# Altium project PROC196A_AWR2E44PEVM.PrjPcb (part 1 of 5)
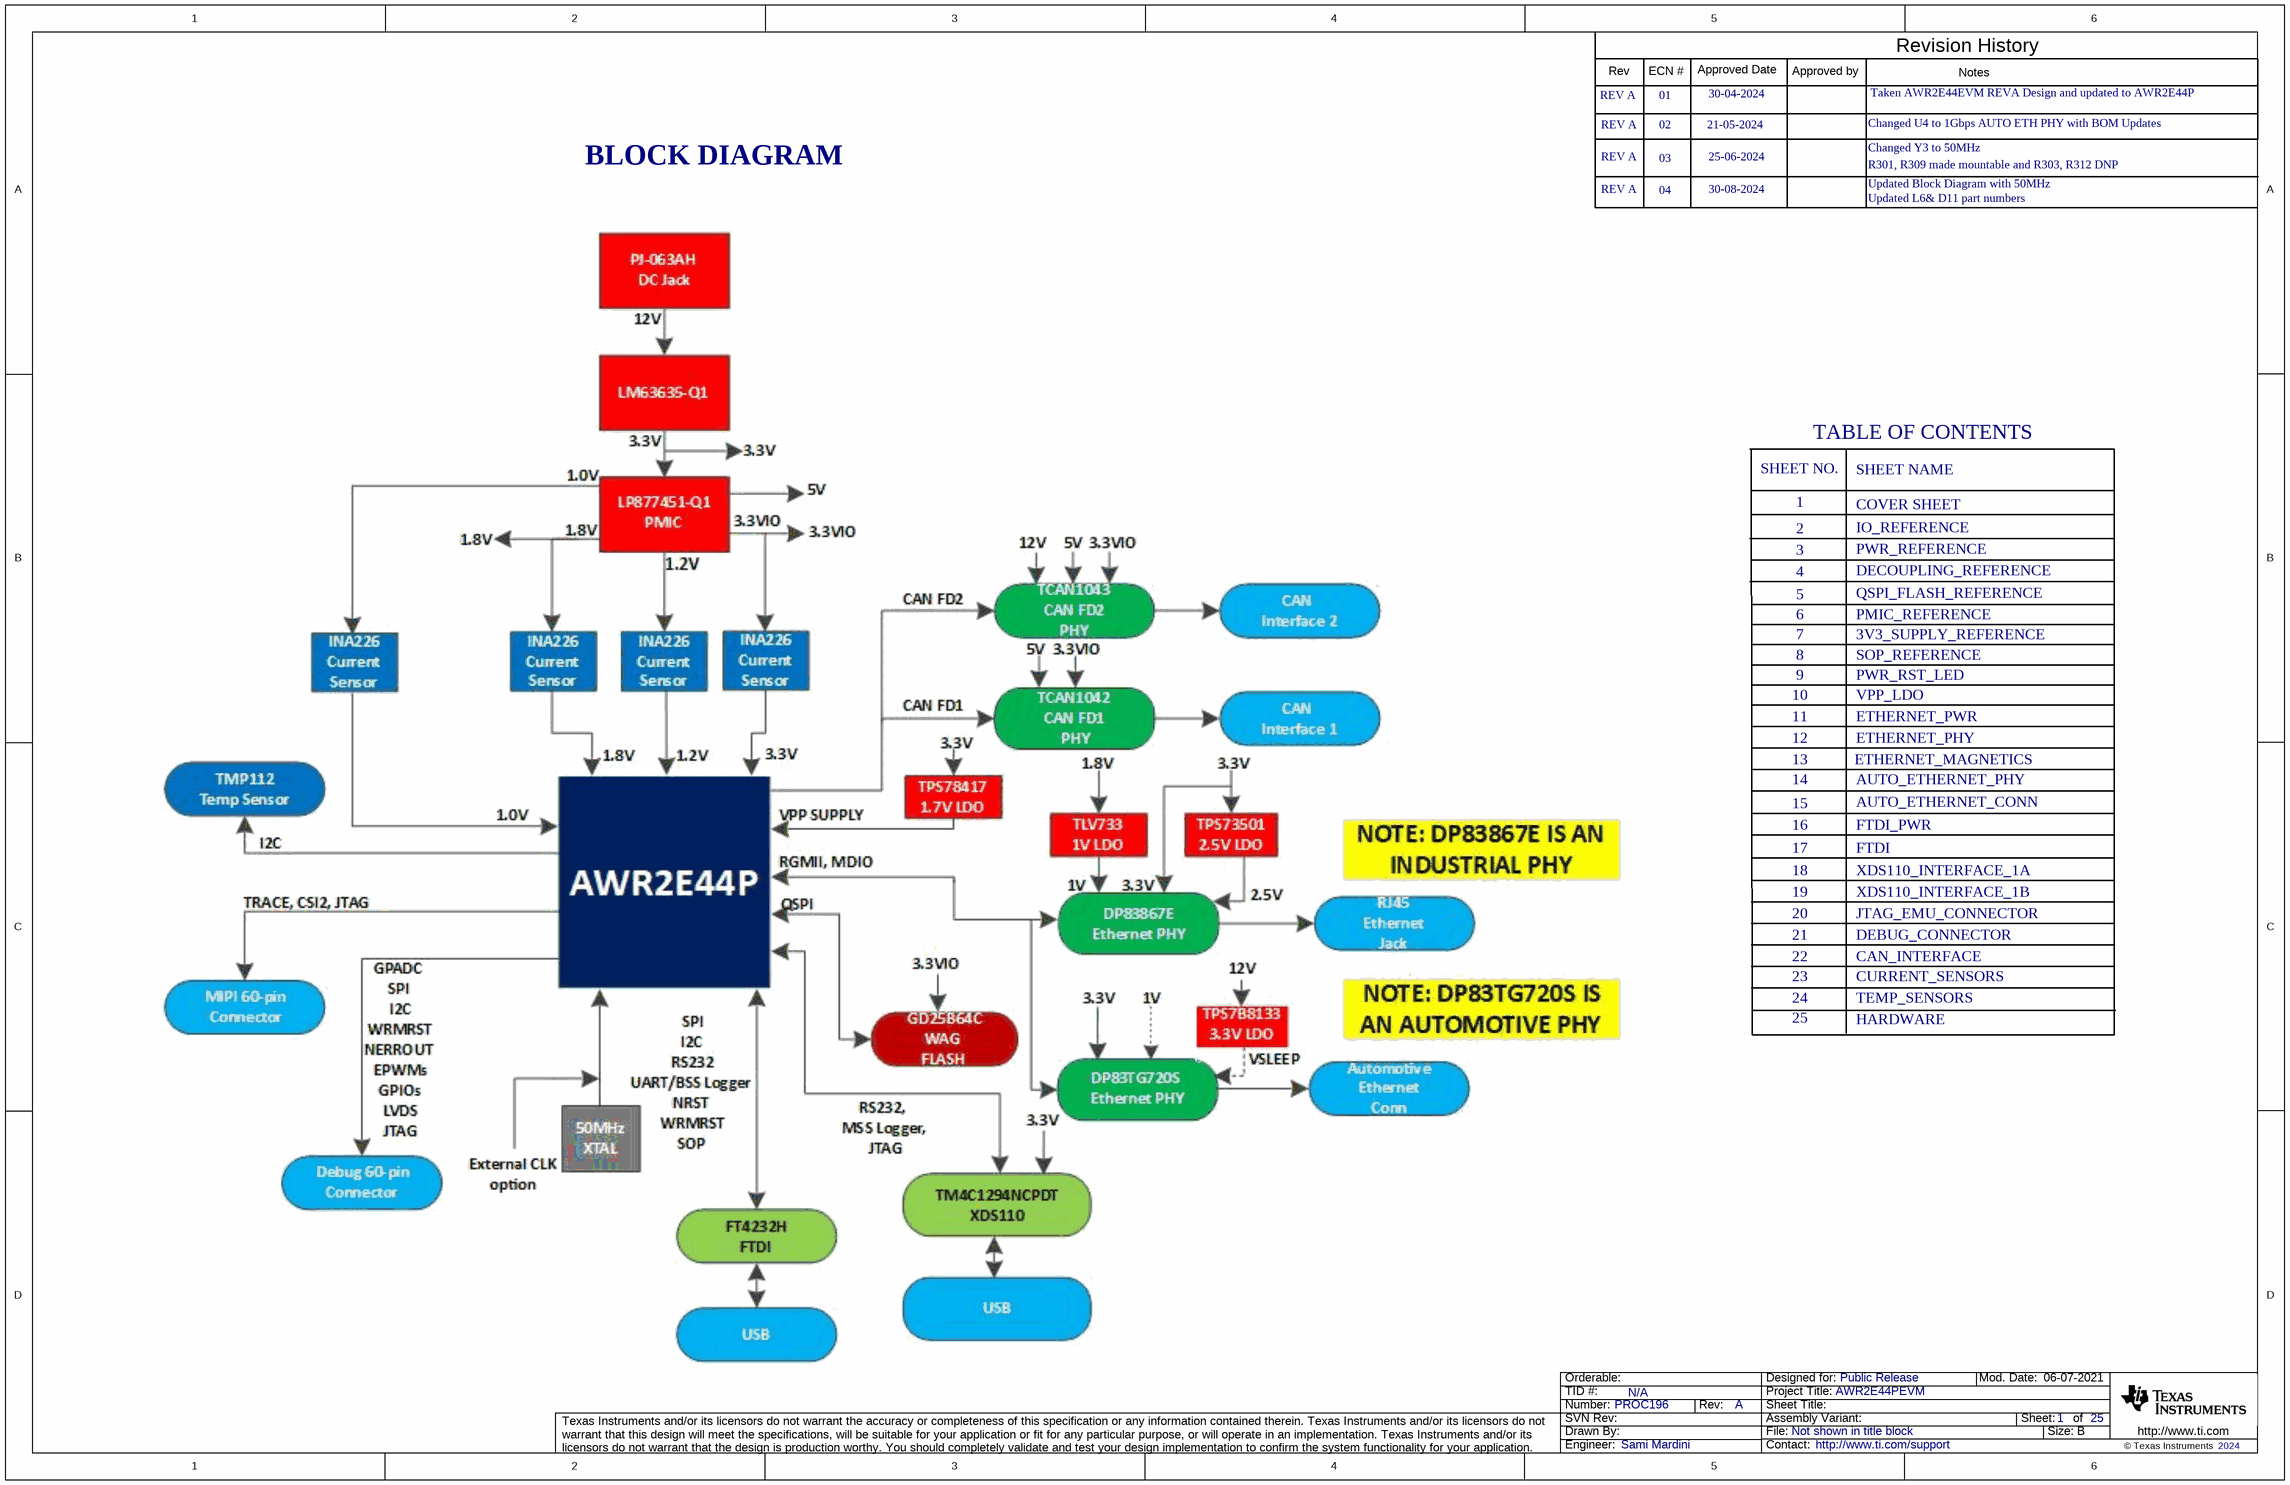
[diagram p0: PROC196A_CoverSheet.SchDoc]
CopyrightYear: 2024; PCB_Layout: Mistral; PCB_Rev: A; PRJ_Customer: Public Release; PRJ_Engineer: Sami Mardini; PRJ_Number: PROC196; PRJ_Title: AWR2E44PEVM; SCH_Rev: A; TechSupport: http://www.ti.com/support; TID: N/A
25 sheets, 736 parts. Net scope: global (net labels, ports and power ports of the same name join across sheets).
Board file: PROC196A_BRD.PcbDoc
Sheets:
  PROC196A_CoverSheet.SchDoc
  PROC196A_IO_Reference.SchDoc
  PROC196A_PWR_Reference.SchDoc
  PROC196A_Decoupling_Reference.SchDoc
  PROC196A_QSPI_Flash_Reference.SchDoc
  PROC196A_PMIC_Reference.SchDoc
  PROC196A_3V3_Supply_Reference.SchDoc
  PROC196A_SOP_Reference.SchDoc
  PROC196A_PWR_RST_LED.SchDoc
  PROC196A_VPP_LDO.SchDoc
  PROC196A_Ethernet_PWR.SchDoc
  PROC196A_Ethernet_PHY.SchDoc
  PROC196A_Ethernet_Magnetics.SchDoc
  PROC196A_Auto_Ethernet_PHY.SchDoc
  PROC196A_Auto_Ethernet_conn.SchDoc
  PROC196A_FTDI_PWR.SchDoc
  PROC196A_FTDI.SchDoc
  PROC196A_XDS110 Interface_1A.SchDoc
  PROC196A_XDS110 Interface_1B.SchDoc
  PROC196A_JTAG_EMU_Connector.SchDoc
  PROC196A_Debug_Connector.SchDoc
  PROC196A_CAN_Interface.SchDoc
  PROC196A_Current_Sensors.SchDoc
  PROC196A_Temp_Sensor.SchDoc
  PROC196A_Hardware.SchDoc

## Sheet PROC196A_CoverSheet.SchDoc
size 431 x 279 mm; Date: Not shown in title block; ApprovedBy: Not shown in title block; CheckedBy: Not shown in title block; Author: Not shown in title block; CompanyName: Not shown in title block; Engineer: Not shown in title block; Organization: Not shown in title block; Address1: Not shown in title block; Address2: Not shown in title block; Address3: Not shown in title block; Address4: Not shown in title block; DocumentNumber: 1; Revision: Use project parameter SCH_Rev; SheetNumber: 1; SheetTotal: 25; PageSetup: Record=PageOptions¦CenterHorizontal=True¦CenterVertical=True¦PrintScale=1.00¦XCorrection=1.00¦YCorrection=1.00¦PrintKind=0¦BorderSize=5000000¦LeftOffset=0¦BottomOffset=0¦Orientation=2¦PaperLength=1000¦PaperWidth=1000¦Scale=100¦PaperSource=15¦PrintQuality=600¦MediaType=1¦DitherType=10¦PaperKind=Letter¦PrintScaleMode=1

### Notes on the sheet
- REV A
- Rev
- 01
- ECN #
- 30-04-2024
- Approved Date
- Approved by
- Taken AWR2E44EVM REVA Design and updated to AWR2E44P
- Revision History
- Notes
- BLOCK DIAGRAM
- 02
- 03
- 21-05-2024
- 25-06-2024
- Changed U4 to 1Gbps AUTO ETH PHY with BOM Updates
- Changed Y3 to 50MHz
- R301, R309 made mountable and R303, R312 DNP
- 04
- 30-08-2024
- Updated Block Diagram with 50MHz
- Updated L6& D11 part numbers
- SHEET NO.
- TABLE OF CONTENTS
- SHEET NAME
- 1
- 2
- 3
- COVER SHEET
- IO_REFERENCE
- PWR_REFERENCE
- 4
- 5
- 6
- DECOUPLING_REFERENCE
- PMIC_REFERENCE
- QSPI_FLASH_REFERENCE
- 10
- 7
- 8
- 9
- PWR_RST_LED
- SOP_REFERENCE
- VPP_LDO
- 3V3_SUPPLY_REFERENCE
- 11
- 12
- 13
- ETHERNET_MAGNETICS
- ETHERNET_PWR
- ETHERNET_PHY
- 15
- 16
- 14
- FTDI_PWR
- AUTO_ETHERNET_CONN
- AUTO_ETHERNET_PHY
- 17
- 18
- 19
- XDS110_INTERFACE_1B
- XDS110_INTERFACE_1A
- FTDI
- 20
- 21
- 22
- JTAG_EMU_CONNECTOR
- DEBUG_CONNECTOR
- CAN_INTERFACE
- 23
- 24
- 25
- HARDWARE
- CURRENT_SENSORS
- TEMP_SENSORS

## Sheet PROC196A_IO_Reference.SchDoc
size A2; Date: Not shown in title block; ApprovedBy: Not shown in title block; CheckedBy: Not shown in title block; Author: Not shown in title block; CompanyName: Not shown in title block; Engineer: Not shown in title block; Organization: Not shown in title block; Address1: Not shown in title block; Address2: Not shown in title block; Address3: Not shown in title block; Address4: Not shown in title block; DocumentNumber: 2; Revision: Use project parameter SCH_Rev; SheetNumber: 2; SheetTotal: 25; PageSetup: Record=PageOptions¦CenterHorizontal=True¦CenterVertical=True¦PrintScale=1.00¦XCorrection=1.00¦YCorrection=1.00¦PrintKind=0¦BorderSize=5000000¦LeftOffset=0¦BottomOffset=0¦Orientation=2¦PaperLength=1000¦PaperWidth=1000¦Scale=100¦PaperSource=15¦PrintQuality=600¦MediaType=1¦DitherType=10¦PaperKind=Letter¦PrintScaleMode=1
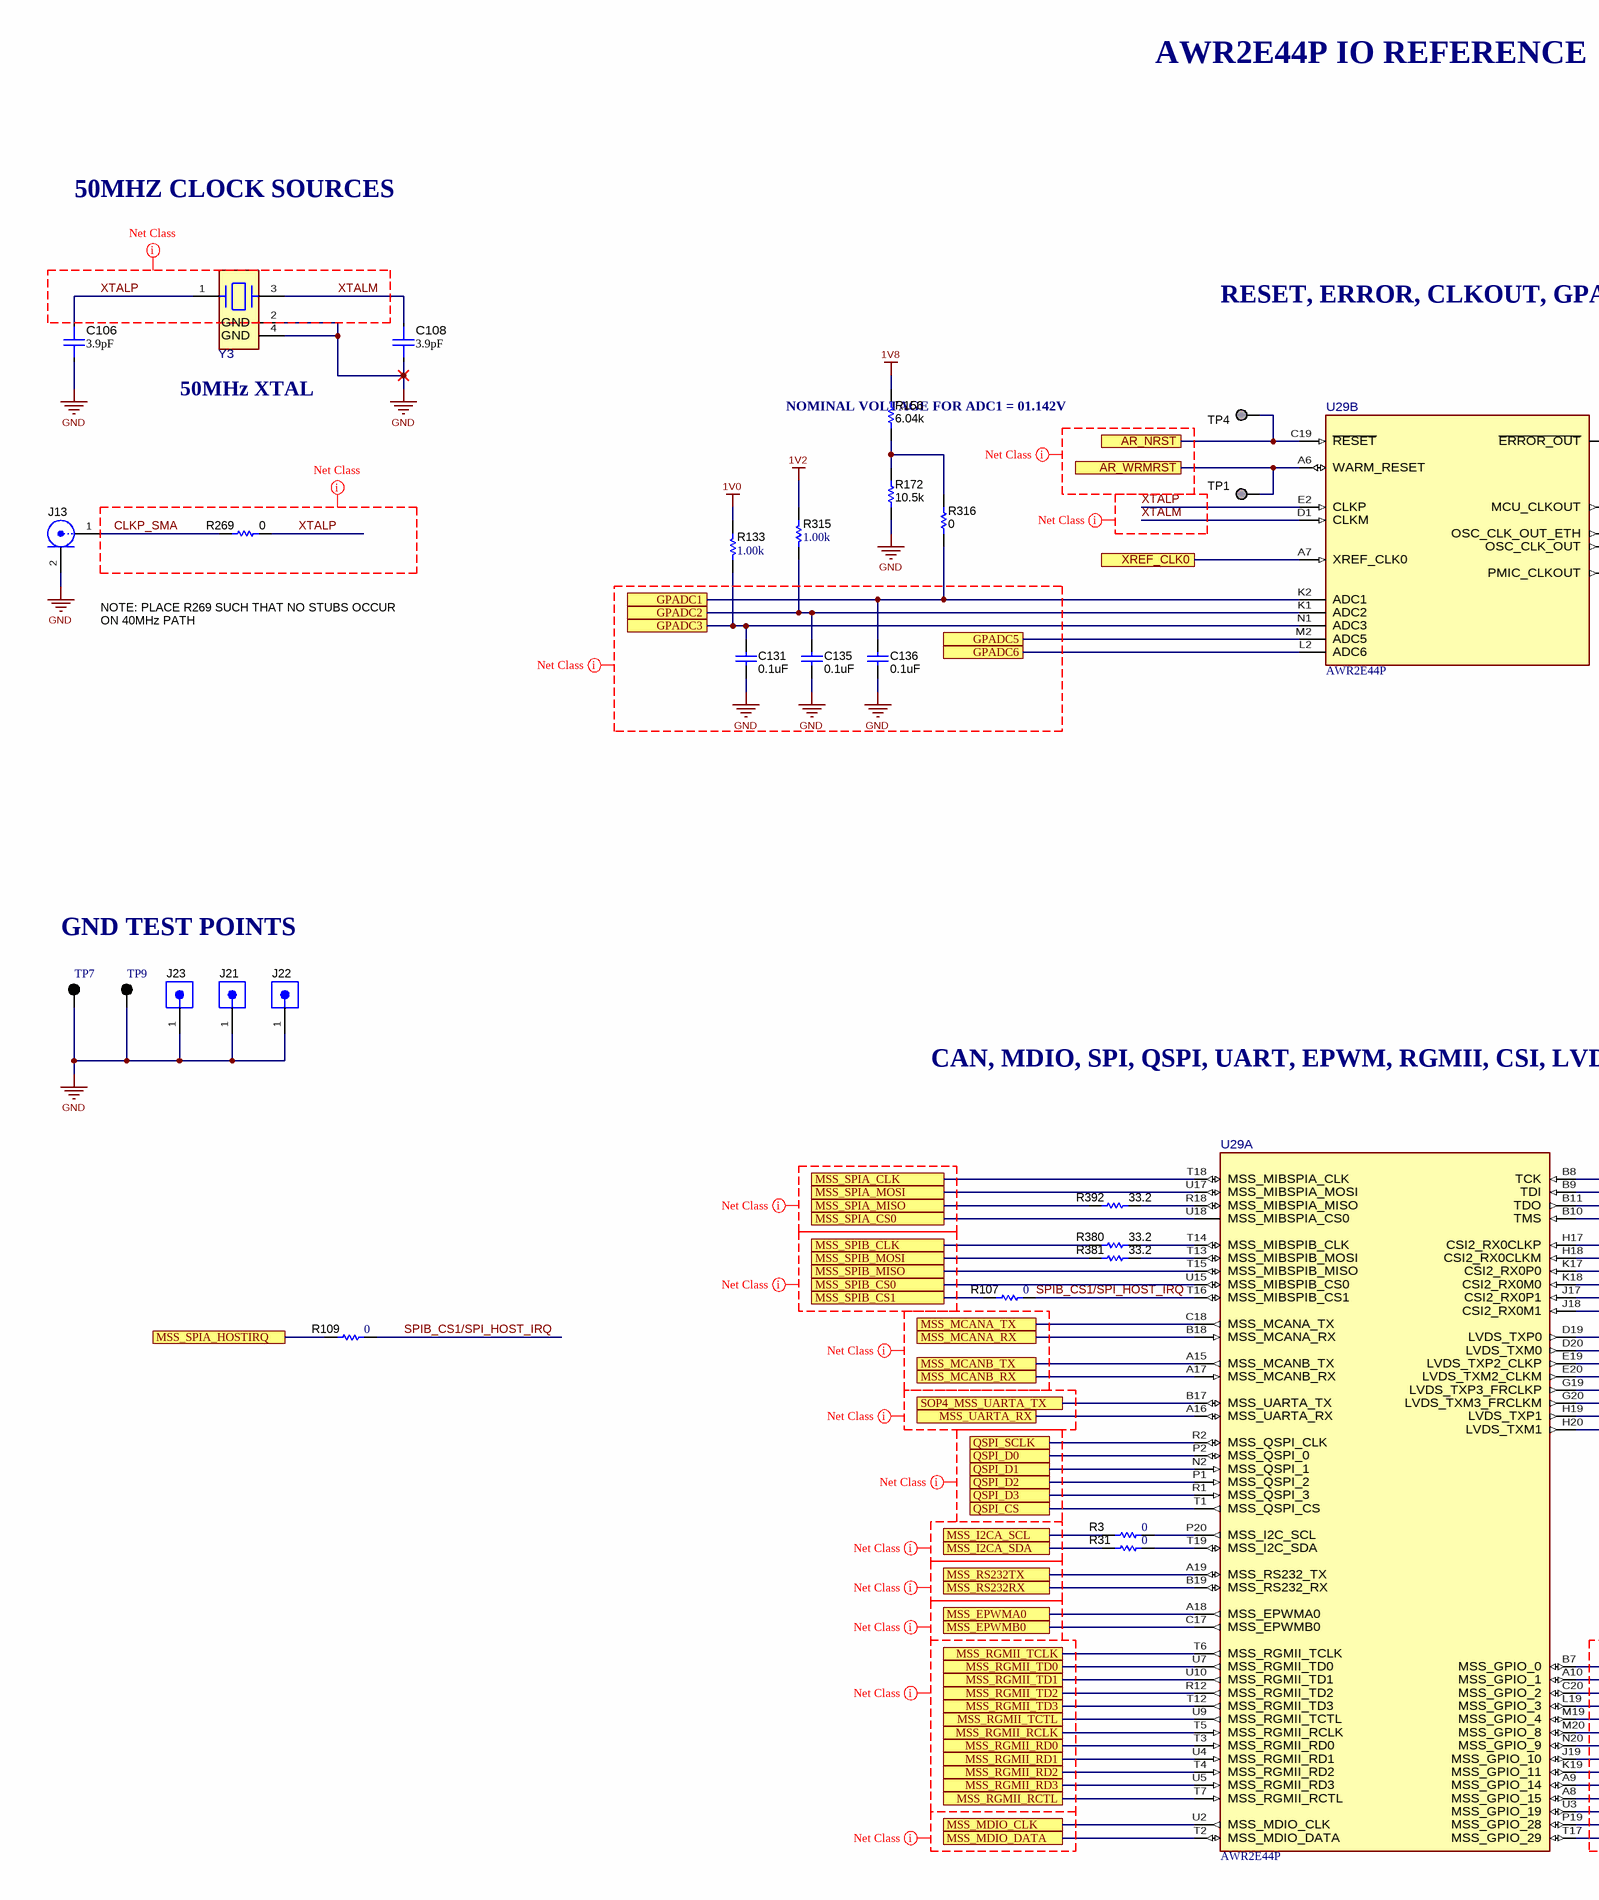
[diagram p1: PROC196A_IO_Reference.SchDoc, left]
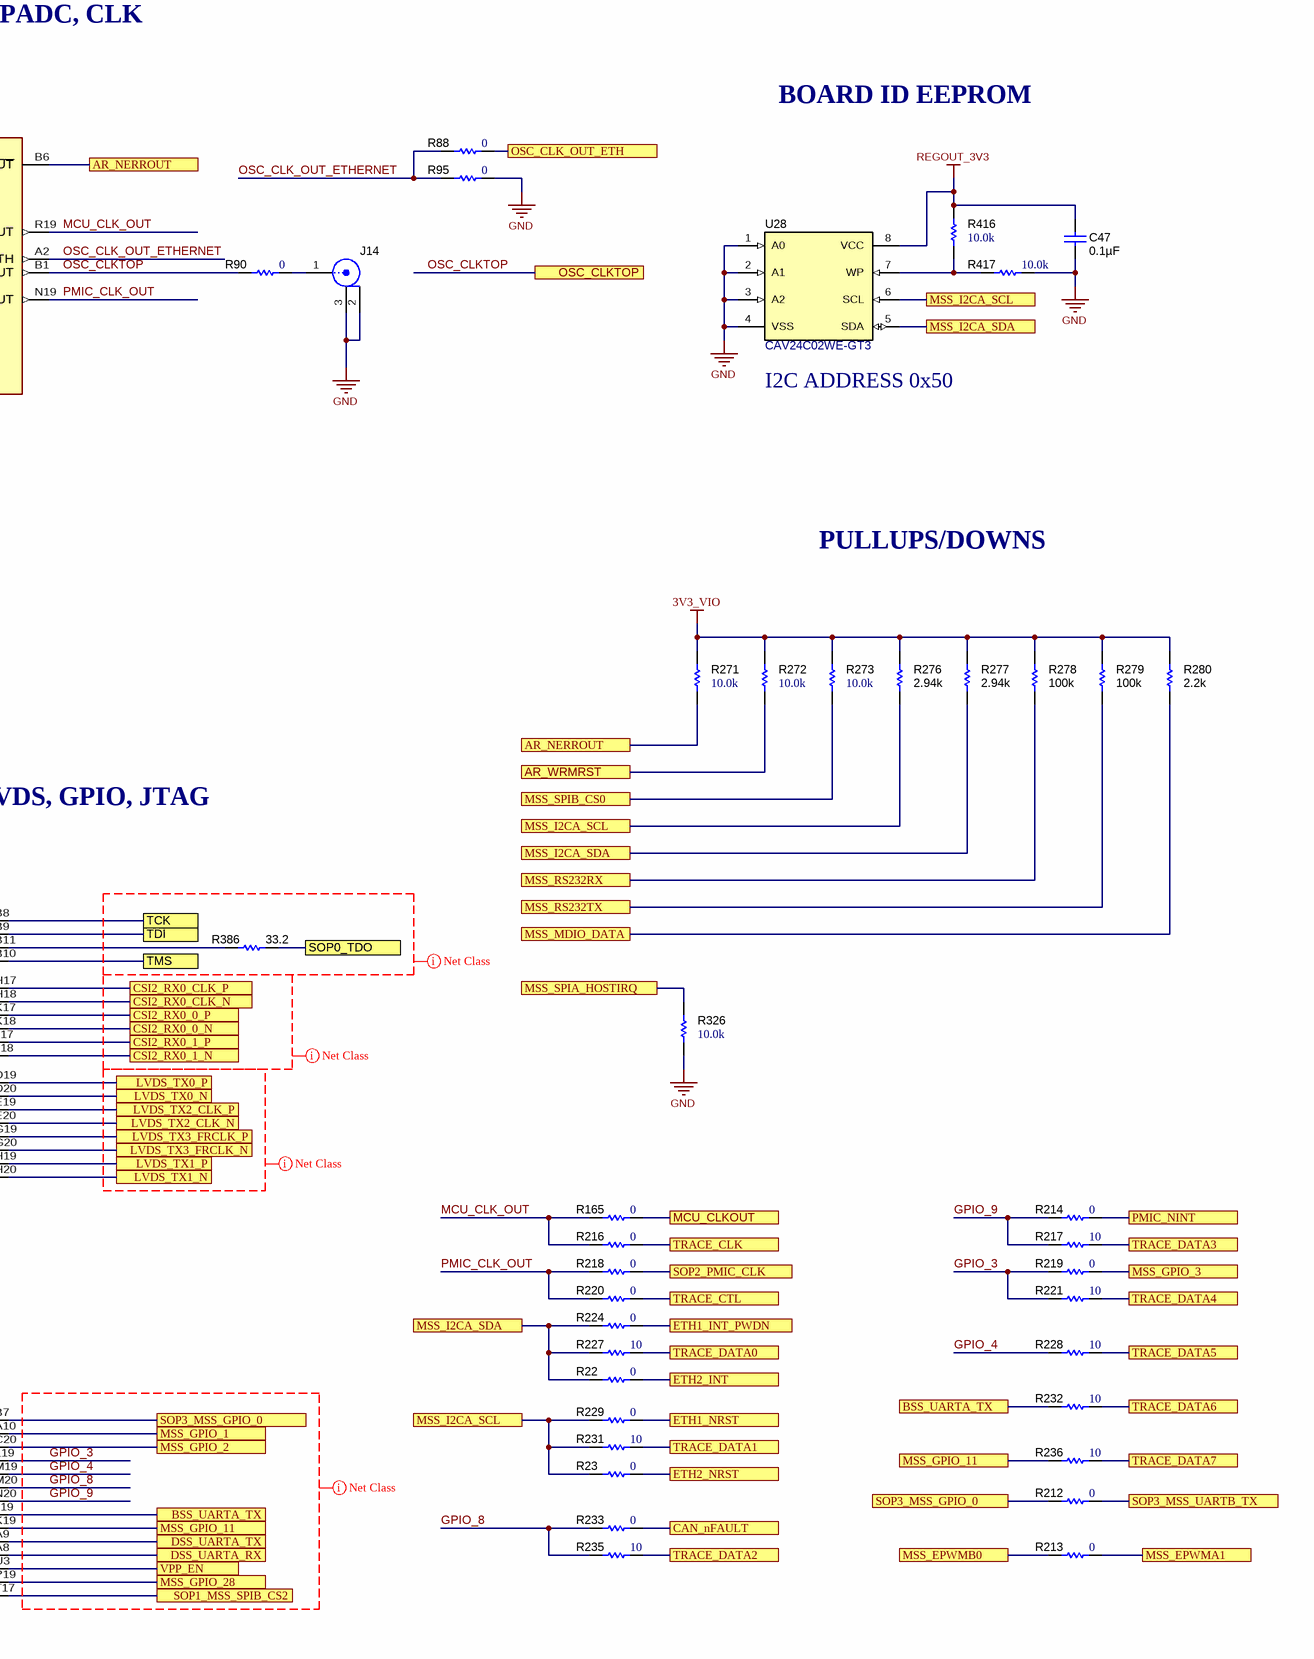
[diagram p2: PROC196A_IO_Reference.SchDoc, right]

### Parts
C47  ValueDisplayed: 0.1µF  [0402L]  (hidden comment: C0402C104K8RACTU)
C106  ValueDisplayed: 3.9pF  [FP-GCM1555C1H3R9BA16D_0402-MFG]  (hidden comment: GCM1555C1H3R9BA16D)
C108  ValueDisplayed: 3.9pF  [FP-GCM1555C1H3R9BA16D_0402-MFG]  (hidden comment: GCM1555C1H3R9BA16D)
C131  ValueDisplayed: 0.1uF  [0402L]  (hidden comment: GCM155R71C104KA55D)
C135  ValueDisplayed: 0.1uF  [0402L]  (hidden comment: GCM155R71C104KA55D)
C136  ValueDisplayed: 0.1uF  [0402L]  (hidden comment: GCM155R71C104KA55D)
J13  142-0711-201  [142-0711-201]  (value not drawn)
J14  128-0711-201  [Johnson_128-0711-201]  (value not drawn)
J21  GBC01SFBN-M30  [Sullins_GBC01SFBN-M30]  (value not drawn)
J22  GBC01SFBN-M30  [Sullins_GBC01SFBN-M30]  (value not drawn)
J23  GBC01SFBN-M30  [Sullins_GBC01SFBN-M30]  (value not drawn)
R3  ValueDisplayed: 0  [0402L]  (hidden comment: ERJ-2GE0R00X)
R22  ValueDisplayed: 0  [0402L]  (hidden comment: ERJ-2GE0R00X)
R23  ValueDisplayed: 0  [0402L]  (hidden comment: ERJ-2GE0R00X)
R31  ValueDisplayed: 0  [0402L]  (hidden comment: ERJ-2GE0R00X)
R88  ValueDisplayed: 0  [0402L]  (hidden comment: ERJ-2GE0R00X)
R90  ValueDisplayed: 0  [0402L]  (hidden comment: ERJ-2GE0R00X)
R95  ValueDisplayed: 0  [0402L]  (hidden comment: ERJ-2GE0R00X)
R107  ValueDisplayed: 0  [0402L]  (hidden comment: ERJ-2GE0R00X)
R109  ValueDisplayed: 0  [0402L]  (hidden comment: ERJ-2GE0R00X)
R133  ValueDisplayed: 1.00k  [0402L]  (hidden comment: CRCW04021K00FKED)
R156  ValueDisplayed: 6.04k  [0402L]  (hidden comment: CRCW04026K04FKED)
R165  ValueDisplayed: 0  [0201L]  (hidden comment: CRCW02010000Z0ED)
R172  ValueDisplayed: 10.5k  [0402L]  (hidden comment: CRCW040210K5FKED)
R212  ValueDisplayed: 0  [0201L]  (hidden comment: CRCW02010000Z0ED)
R213  value 0  [0402L]  (hidden comment: ERJ-2GE0R00X)
R214  value 0  [0402L]  (hidden comment: ERJ-2GE0R00X)
R216  ValueDisplayed: 0  [0201L]  (hidden comment: CRCW02010000Z0ED)
R217  ValueDisplayed: 10  [0201L]  (hidden comment: RC0201JR-0710RL)
R218  ValueDisplayed: 0  [0201L]  (hidden comment: CRCW02010000Z0ED)
R219  ValueDisplayed: 0  [0201L]  (hidden comment: CRCW02010000Z0ED)
R220  ValueDisplayed: 0  [0201L]  (hidden comment: CRCW02010000Z0ED)
R221  ValueDisplayed: 10  [0201L]  (hidden comment: RC0201JR-0710RL)
R224  ValueDisplayed: 0  [0201L]  (hidden comment: CRCW02010000Z0ED)
R227  ValueDisplayed: 10  [0201L]  (hidden comment: RC0201JR-0710RL)
R228  ValueDisplayed: 10  [0201L]  (hidden comment: RC0201JR-0710RL)
R229  ValueDisplayed: 0  [0201L]  (hidden comment: CRCW02010000Z0ED)
R231  ValueDisplayed: 10  [0201L]  (hidden comment: RC0201JR-0710RL)
R232  ValueDisplayed: 10  [0201L]  (hidden comment: RC0201JR-0710RL)
R233  value 0  [0402L]  (hidden comment: ERJ-2GE0R00X)
R235  ValueDisplayed: 10  [0201L]  (hidden comment: RC0201JR-0710RL)
R236  ValueDisplayed: 10  [0201L]  (hidden comment: RC0201JR-0710RL)
R269  ValueDisplayed: 0  [0402L]  (hidden comment: ERJ-2GE0R00X)
R271  ValueDisplayed: 10.0k  [0402L]  (hidden comment: CRCW040210K0FKED)
R272  ValueDisplayed: 10.0k  [0402L]  (hidden comment: CRCW040210K0FKED)
R273  ValueDisplayed: 10.0k  [0402L]  (hidden comment: CRCW040210K0FKED)
R276  ValueDisplayed: 2.94k  [0402L]  (hidden comment: CRCW04022K94FKED)
R277  ValueDisplayed: 2.94k  [0402L]  (hidden comment: CRCW04022K94FKED)
R278  ValueDisplayed: 100k  [0402L]  (hidden comment: CRCW0402100KFKED)
R279  ValueDisplayed: 100k  [0402L]  (hidden comment: CRCW0402100KFKED)
R280  ValueDisplayed: 2.2k  [0402L]  (hidden comment: CRCW04022K20JNED)
R315  ValueDisplayed: 1.00k  [0402L]  (hidden comment: CRCW04021K00FKED)
R316  ValueDisplayed: 0  [0402L]  (hidden comment: ERJ-2GE0R00X)
R326  ValueDisplayed: 10.0k  [0402L]  (hidden comment: CRCW040210K0FKED)
R380  ValueDisplayed: 33.2  [0402L]  (hidden comment: CRCW040233R2FKED)
R381  ValueDisplayed: 33.2  [0402L]  (hidden comment: CRCW040233R2FKED)
R386  ValueDisplayed: 33.2  [0402L]  (hidden comment: CRCW040233R2FKED)
R392  ValueDisplayed: 33.2  [0402L]  (hidden comment: CRCW040233R2FKED)
R416  ValueDisplayed: 10.0k  [0402L]  (hidden comment: CRCW040210K0FKED)
R417  ValueDisplayed: 10.0k  [0402L]  (hidden comment: CRCW040210K0FKED)
TP1  TESTPOINT  [TP_25MIL-SMT]  (value not drawn)  (no BOM)
TP4  TESTPOINT  [TP_25MIL-SMT]  (value not drawn)  (no BOM)
TP7  5001  [Keystone5001]  (value not drawn)
TP9  5001  [Keystone5001]  (value not drawn)
U28  CAV24C02WE-GT3  [SOIC-8]
U29  AWR2E44P  [AMX0278A-MFG]  (parts A,B of 6)
Y3  NX2016SA-50M-STD-CZS-3  [FP-NX2016SA-50M-STD-CZS-3_SMT4_2MM0_1MM6-MFG]  (value not drawn)

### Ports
AR_NERROUT, AR_NRST, AR_WRMRST, BSS_UARTA_TX, CAN_nFAULT, CSI2_RX0_0_N, CSI2_RX0_0_P, CSI2_RX0_1_N, CSI2_RX0_1_P, CSI2_RX0_CLK_N, CSI2_RX0_CLK_P, DSS_UARTA_RX, DSS_UARTA_TX, ETH1_INT_PWDN, ETH1_NRST, ETH2_INT, ETH2_NRST, GPADC1, GPADC2, GPADC3, GPADC5, GPADC6, LVDS_TX0_N, LVDS_TX0_P, LVDS_TX1_N, LVDS_TX1_P, LVDS_TX2_CLK_N, LVDS_TX2_CLK_P, LVDS_TX3_FRCLK_N, LVDS_TX3_FRCLK_P, MCU_CLKOUT, MSS_EPWMA0, MSS_EPWMA1, MSS_EPWMB0, MSS_GPIO_1, MSS_GPIO_2, MSS_GPIO_3, MSS_GPIO_11, MSS_GPIO_28, MSS_I2CA_SCL, MSS_I2CA_SDA, MSS_MCANA_RX, MSS_MCANA_TX, MSS_MCANB_RX, MSS_MCANB_TX, MSS_MDIO_CLK, MSS_MDIO_DATA, MSS_RGMII_RCLK, MSS_RGMII_RCTL, MSS_RGMII_RD0, MSS_RGMII_RD1, MSS_RGMII_RD2, MSS_RGMII_RD3, MSS_RGMII_TCLK, MSS_RGMII_TCTL, MSS_RGMII_TD0, MSS_RGMII_TD1, MSS_RGMII_TD2, MSS_RGMII_TD3, MSS_RS232RX, MSS_RS232TX, MSS_SPIA_CLK, MSS_SPIA_CS0, MSS_SPIA_HOSTIRQ, MSS_SPIA_MISO, MSS_SPIA_MOSI, MSS_SPIB_CLK, MSS_SPIB_CS0, MSS_SPIB_CS1, MSS_SPIB_MISO, MSS_SPIB_MOSI, MSS_UARTA_RX, OSC_CLK_OUT_ETH, OSC_CLKTOP, PMIC_NINT, QSPI_CS, QSPI_D0, QSPI_D1, QSPI_D2, QSPI_D3, QSPI_SCLK, SOP0_TDO, SOP1_MSS_SPIB_CS2, SOP2_PMIC_CLK, SOP3_MSS_GPIO_0, SOP3_MSS_UARTB_TX, SOP4_MSS_UARTA_TX, TCK, TDI, TMS, TRACE_CLK, TRACE_CTL, TRACE_DATA0, TRACE_DATA1, TRACE_DATA2, TRACE_DATA3, TRACE_DATA4, TRACE_DATA5, TRACE_DATA6, TRACE_DATA7, VPP_EN, XREF_CLK0

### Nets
1V0: R133.2
1V2: R315.2
1V8: R156.2
3V3_VIO: R271.2 R272.2 R273.2 R276.2 R277.2 R278.2 R279.2 R280.2
GND: C47.1 C106.2 C108.2 C131.1 C135.1 C136.1 J13.2 J14.2 J14.3 J21.1 J22.1 J23.1 R95.1 R172.1 R326.1 R417.1 TP7.1 TP9.1 U28.1(A0) U28.2(A1) U28.3(A2) U28.4(VSS) Y3.2(GND) Y3.4(GND)
REGOUT_3V3: C47.2 R416.2 U28.8(VCC)
AR_NERROUT: R271.1 U29.B6(~{ERROR_OUT}) ; port AR_NERROUT
AR_NRST: TP4.1 U29.C19(~{RESET}) ; port AR_NRST
AR_WRMRST: R272.1 TP1.1 U29.A6(WARM_RESET) ; port AR_WRMRST
BSS_UARTA_TX: R232.2 U29.J19(MSS_GPIO_10) ; port BSS_UARTA_TX
CAN_nFAULT: R233.2 ; port CAN_nFAULT
CLKP_SMA: J13.1 R269.2
CSI2_RX0_0_N: U29.K18(CSI2_RX0M0) ; port CSI2_RX0_0_N
CSI2_RX0_0_P: U29.K17(CSI2_RX0P0) ; port CSI2_RX0_0_P
CSI2_RX0_1_N: U29.J18(CSI2_RX0M1) ; port CSI2_RX0_1_N
CSI2_RX0_1_P: U29.J17(CSI2_RX0P1) ; port CSI2_RX0_1_P
CSI2_RX0_CLK_N: U29.H18(CSI2_RX0CLKM) ; port CSI2_RX0_CLK_N
CSI2_RX0_CLK_P: U29.H17(CSI2_RX0CLKP) ; port CSI2_RX0_CLK_P
DSS_UARTA_RX: U29.A8(MSS_GPIO_15) ; port DSS_UARTA_RX
DSS_UARTA_TX: U29.A9(MSS_GPIO_14) ; port DSS_UARTA_TX
ETH1_INT_PWDN: R224.2 ; port ETH1_INT_PWDN
ETH1_NRST: R229.2 ; port ETH1_NRST
ETH2_INT: R22.1 ; port ETH2_INT
ETH2_NRST: R23.1 ; port ETH2_NRST
GPADC1: C136.2 R316.1 U29.K2(ADC1) ; port GPADC1
GPADC2: C135.2 R315.1 U29.K1(ADC2) ; port GPADC2
GPADC3: C131.2 R133.1 U29.N1(ADC3) ; port GPADC3
GPADC5: U29.M2(ADC5) ; port GPADC5
GPADC6: U29.L2(ADC6) ; port GPADC6
GPIO_3: R219.1 R221.2 U29.L19(MSS_GPIO_3)
GPIO_4: R228.2 U29.M19(MSS_GPIO_4)
GPIO_8: R233.1 R235.2 U29.M20(MSS_GPIO_8)
GPIO_9: R214.1 R217.2 U29.N20(MSS_GPIO_9)
LVDS_TX0_N: U29.D20(LVDS_TXM0) ; port LVDS_TX0_N
LVDS_TX0_P: U29.D19(LVDS_TXP0) ; port LVDS_TX0_P
LVDS_TX1_N: U29.H20(LVDS_TXM1) ; port LVDS_TX1_N
LVDS_TX1_P: U29.H19(LVDS_TXP1) ; port LVDS_TX1_P
LVDS_TX2_CLK_N: U29.E20(LVDS_TXM2_CLKM) ; port LVDS_TX2_CLK_N
LVDS_TX2_CLK_P: U29.E19(LVDS_TXP2_CLKP) ; port LVDS_TX2_CLK_P
LVDS_TX3_FRCLK_N: U29.G20(LVDS_TXM3_FRCLKM) ; port LVDS_TX3_FRCLK_N
LVDS_TX3_FRCLK_P: U29.G19(LVDS_TXP3_FRCLKP) ; port LVDS_TX3_FRCLK_P
MCU_CLK_OUT: R165.1 R216.1 U29.R19(MCU_CLKOUT)
MCU_CLKOUT: R165.2 ; port MCU_CLKOUT
MSS_EPWMA0: U29.A18(MSS_EPWMA0) ; port MSS_EPWMA0
MSS_EPWMA1: R213.2 ; port MSS_EPWMA1
MSS_EPWMB0: R213.1 U29.C17(MSS_EPWMB0) ; port MSS_EPWMB0
MSS_GPIO_1: U29.A10(MSS_GPIO_1) ; port MSS_GPIO_1
MSS_GPIO_2: U29.C20(MSS_GPIO_2) ; port MSS_GPIO_2
MSS_GPIO_3: R219.2 ; port MSS_GPIO_3
MSS_GPIO_11: R236.2 U29.K19(MSS_GPIO_11) ; port MSS_GPIO_11
MSS_GPIO_28: U29.P19(MSS_GPIO_28) ; port MSS_GPIO_28
MSS_I2CA_SCL: R3.1 R23.2 R229.1 R231.2 R276.1 U28.6(SCL) ; port MSS_I2CA_SCL
MSS_I2CA_SDA: R22.2 R31.1 R224.1 R227.2 R277.1 U28.5(SDA) ; port MSS_I2CA_SDA
MSS_MCANA_RX: U29.B18(MSS_MCANA_RX) ; port MSS_MCANA_RX
MSS_MCANA_TX: U29.C18(MSS_MCANA_TX) ; port MSS_MCANA_TX
MSS_MCANB_RX: U29.A17(MSS_MCANB_RX) ; port MSS_MCANB_RX
MSS_MCANB_TX: U29.A15(MSS_MCANB_TX) ; port MSS_MCANB_TX
MSS_MDIO_CLK: U29.U2(MSS_MDIO_CLK) ; port MSS_MDIO_CLK
MSS_MDIO_DATA: R280.1 U29.T2(MSS_MDIO_DATA) ; port MSS_MDIO_DATA
MSS_RGMII_RCLK: U29.T5(MSS_RGMII_RCLK) ; port MSS_RGMII_RCLK
MSS_RGMII_RCTL: U29.T7(MSS_RGMII_RCTL) ; port MSS_RGMII_RCTL
MSS_RGMII_RD0: U29.T3(MSS_RGMII_RD0) ; port MSS_RGMII_RD0
MSS_RGMII_RD1: U29.U4(MSS_RGMII_RD1) ; port MSS_RGMII_RD1
MSS_RGMII_RD2: U29.T4(MSS_RGMII_RD2) ; port MSS_RGMII_RD2
MSS_RGMII_RD3: U29.U5(MSS_RGMII_RD3) ; port MSS_RGMII_RD3
MSS_RGMII_TCLK: U29.T6(MSS_RGMII_TCLK) ; port MSS_RGMII_TCLK
MSS_RGMII_TCTL: U29.U9(MSS_RGMII_TCTL) ; port MSS_RGMII_TCTL
MSS_RGMII_TD0: U29.U7(MSS_RGMII_TD0) ; port MSS_RGMII_TD0
MSS_RGMII_TD1: U29.U10(MSS_RGMII_TD1) ; port MSS_RGMII_TD1
MSS_RGMII_TD2: U29.R12(MSS_RGMII_TD2) ; port MSS_RGMII_TD2
MSS_RGMII_TD3: U29.T12(MSS_RGMII_TD3) ; port MSS_RGMII_TD3
MSS_RS232RX: R278.1 U29.B19(MSS_RS232_RX) ; port MSS_RS232RX
MSS_RS232TX: R279.1 U29.A19(MSS_RS232_TX) ; port MSS_RS232TX
MSS_SPIA_CLK: U29.T18(MSS_MIBSPIA_CLK) ; port MSS_SPIA_CLK
MSS_SPIA_CS0: U29.U18(MSS_MIBSPIA_CS0) ; port MSS_SPIA_CS0
MSS_SPIA_HOSTIRQ: R109.1 R326.2 ; port MSS_SPIA_HOSTIRQ
MSS_SPIA_MISO: R392.1 ; port MSS_SPIA_MISO
MSS_SPIA_MOSI: U29.U17(MSS_MIBSPIA_MOSI) ; port MSS_SPIA_MOSI
MSS_SPIB_CLK: R380.1 ; port MSS_SPIB_CLK
MSS_SPIB_CS0: R273.1 U29.U15(MSS_MIBSPIB_CS0) ; port MSS_SPIB_CS0
MSS_SPIB_CS1: R107.1 ; port MSS_SPIB_CS1
MSS_SPIB_MISO: U29.T15(MSS_MIBSPIB_MISO) ; port MSS_SPIB_MISO
MSS_SPIB_MOSI: R381.1 ; port MSS_SPIB_MOSI
MSS_UARTA_RX: U29.A16(MSS_UARTA_RX) ; port MSS_UARTA_RX
OSC_CLK_OUT_ETH: R88.1 ; port OSC_CLK_OUT_ETH
OSC_CLK_OUT_ETHERNET: R88.2 R95.2 U29.A2(OSC_CLK_OUT_ETH)
OSC_CLKTOP: R90.1 U29.B1(OSC_CLK_OUT) ; port OSC_CLKTOP
PMIC_CLK_OUT: R218.1 R220.1 U29.N19(PMIC_CLKOUT)
PMIC_NINT: R214.2 ; port PMIC_NINT
QSPI_CS: U29.T1(MSS_QSPI_CS) ; port QSPI_CS
QSPI_D0: U29.P2(MSS_QSPI_0) ; port QSPI_D0
QSPI_D1: U29.N2(MSS_QSPI_1) ; port QSPI_D1
QSPI_D2: U29.P1(MSS_QSPI_2) ; port QSPI_D2
QSPI_D3: U29.R1(MSS_QSPI_3) ; port QSPI_D3
QSPI_SCLK: U29.R2(MSS_QSPI_CLK) ; port QSPI_SCLK
SOP0_TDO: R386.1 ; port SOP0_TDO
SOP1_MSS_SPIB_CS2: U29.T17(MSS_GPIO_29) ; port SOP1_MSS_SPIB_CS2
SOP2_PMIC_CLK: R218.2 ; port SOP2_PMIC_CLK
SOP3_MSS_GPIO_0: R212.1 U29.B7(MSS_GPIO_0) ; port SOP3_MSS_GPIO_0
SOP3_MSS_UARTB_TX: R212.2 ; port SOP3_MSS_UARTB_TX
SOP4_MSS_UARTA_TX: U29.B17(MSS_UARTA_TX) ; port SOP4_MSS_UARTA_TX
SPIB_CS1/SPI_HOST_IRQ: R107.2 R109.2 U29.T16(MSS_MIBSPIB_CS1)
TCK: U29.B8(TCK) ; port TCK
TDI: U29.B9(TDI) ; port TDI
TMS: U29.B10(TMS) ; port TMS
TRACE_CLK: R216.2 ; port TRACE_CLK
TRACE_CTL: R220.2 ; port TRACE_CTL
TRACE_DATA0: R227.1 ; port TRACE_DATA0
TRACE_DATA1: R231.1 ; port TRACE_DATA1
TRACE_DATA2: R235.1 ; port TRACE_DATA2
TRACE_DATA3: R217.1 ; port TRACE_DATA3
TRACE_DATA4: R221.1 ; port TRACE_DATA4
TRACE_DATA5: R228.1 ; port TRACE_DATA5
TRACE_DATA6: R232.1 ; port TRACE_DATA6
TRACE_DATA7: R236.1 ; port TRACE_DATA7
VPP_EN: U29.U3(MSS_GPIO_19) ; port VPP_EN
XREF_CLK0: U29.A7(XREF_CLK0) ; port XREF_CLK0
XTALM: C108.1 U29.D1(CLKM) Y3.3(2_XTAL)
XTALP: C106.1 R269.1 U29.E2(CLKP) Y3.1(1_XTAL)
NetJ14_1: J14.1 R90.2
NetR3_2: R3.2 U29.P20(MSS_I2C_SCL)
NetR31_2: R31.2 U29.T19(MSS_I2C_SDA)
NetR156_1: R156.1 R172.2 R316.2
NetR380_2: R380.2 U29.T14(MSS_MIBSPIB_CLK)
NetR381_2: R381.2 U29.T13(MSS_MIBSPIB_MOSI)
NetR386_2: R386.2 U29.B11(TDO)
NetR392_2: R392.2 U29.R18(MSS_MIBSPIA_MISO)
NetR416_1: R416.1 R417.2 U28.7(WP)

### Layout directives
net class CAN: (no net found under the mark)
net class 40MHz_CLK: CLKP_SMA, XTALM, XTALP
net class RGMII_TX_RX: (no net found under the mark)
net class GPADC: GND
net class I2C: (no net found under the mark)
net class MSS_SPIA: (no net found under the mark)
net class MSS_SPIB: (no net found under the mark)
net class QSPI: (no net found under the mark)
net class CSI: (no net found under the mark)
net class EPWM: (no net found under the mark)
net class JTAG: (no net found under the mark)
net class RESET: (no net found under the mark)
net class LVDS: (no net found under the mark)
net class UART: (no net found under the mark)
net class GPIO: GPIO_3, GPIO_4, GPIO_8, GPIO_9
net class MDIO: (no net found under the mark)

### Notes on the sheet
- AWR2E44P IO REFERENCE
- 50MHZ CLOCK SOURCES
- RESET, ERROR, CLKOUT, GPADC, CLK
- (near Y3) 50MHz XTAL
- NOMINAL VOLTAGE FOR ADC1 = 01.142V
- BOARD ID EEPROM
- NOTE: PLACE R269 SUCH THAT NO STUBS OCCUR ON 40MHz PATH
- (near U28) I2C ADDRESS 0x50
- PULLUPS/DOWNS
- GND TEST POINTS
- CAN, MDIO, SPI, QSPI, UART, EPWM, RGMII, CSI, LVDS, GPIO, JTAG

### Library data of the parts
C47 = CMP-0078241-1: CAP, CERM, 0.1 µF, 10 V,+/- 10%, X7R, 0402; Manufacturer: Kemet; TaMin_C: -55°C; Polarized: N; SizeAreaWB_mm2: 3; U/M: EA; Value: 0.1uF; TaMax_C: 125°C; SizeZ_mm: 0.6; SizeX_mm: 1; SizeY_mm: 0.5; Cap_Case: 0402; Value2: 10V; Cap_F: 100nF; AEC Category: Q200
C106 C108 = CMP-0048219-1: Ceramic Capacitor for Automotive 3.9pF ±0.1pF 50VDC C0G 0402 Paper T/R; Manufacturer: Murata; AEC Grade: Grade 1; AEC Qualified: Yes; SizeZ_mm: 0.55mm; TempCo: 30ppm/°C; VDC_V: 50V
C131 C135 C136 = CMP-0006351-2: CAP, CERM, 0.1 uF, 16 V, +/- 10%, X7R, 0402; Manufacturer: MuRata; TaMin_C: -55°C; Polarized: N; SizeAreaWB_mm2: 3; Value1: Unknown; U/M: EA; Value: 0.1uF; TaMax_C: 125°C; SizeZ_mm: 0.6; SizeX_mm: 1; SizeY_mm: 0.5; Cap_Case: 0402; Value2: 16V; CompType: Capacitor; Cap_F: 100nF; AEC Category: Q200
J13 = CMP-0055823-2: Connector, SMA Jack, Vertical, Gold, SMD; Manufacturer: Cinch Connectivity; Green_REACh: Incomplete; Green_Lifecycle: Not Set; Gender: Female
J14 = CMP-0055788-1: UMC Straight Jack Receptacle, 50 Ohm, Gold, SMT; Manufacturer: Cinch Connectivity; CNHeader: FALSE; Gender: Female
J21-J23 = CMP-0084373-1: Header, 1x1, Gold, SMT; Manufacturer: Sullins Connector Solutions; Cert_UL: Y; Current_A: 3A; Gender: Male; Row_Count: 1; Shrouded: N
R3 R22 R23 R31 R88 R90 R95 R107 R109 R269 R316 = CMP-0026992-3: RES, 0, 5%, 0.1 W, AEC-Q200 Grade 0, 0402; Manufacturer: Panasonic; Power_W: 100mW; TempCo: 600 ppm/C; Value_Code: 0000; Value: 0; EIA_Code: E24; SizeX_mm: 1; SizeY_mm: 0.5; SizeZ_mm: 0.6; Value2: 0.1W; AEC Qualified: Y; VDC_V: 50V; AEC Category: Q200; SizeAreaWB_mm2: 3
R133 R315 = CMP-0026071-3: RES, 1.00 k, 1%, 0.063 W, AEC-Q200 Grade 0, 0402; Manufacturer: Vishay-Dale; Power_W: 63mW; TempCo: 100 ppm/C; Value_Code: 1k00; Value: 1.00k; EIA_Code: E96; Res_ohm: 1k; SizeX_mm: 1; SizeY_mm: 0.5; SizeZ_mm: 0.6; Value2: 0.063W; AEC Qualified: Y; VDC_V: 50V; AEC Category: Q200; AEC Grade: 0
R156 = CMP-0026512-2: RES, 6.04 k, 1%, 0.063 W, AEC-Q200 Grade 0, 0402; Manufacturer: Vishay-Dale; Power_W: 63mW; TempCo: 100 ppm/C; Value_Code: 6k04; Value: 6.04k; EIA_Code: E96; SizeX_mm: 1; SizeY_mm: 0.5; SizeZ_mm: 0.6; Value2: 0.063W; AEC Qualified: Y; VDC_V: 50V; AEC Category: Q200; AEC Grade: 0
R165 R212 R216 R218-R220 R224 R229 = CMP-0027008-4: RES, 0, 5%, 0.05 W, 0201; Manufacturer: Vishay-Dale; Power_W: 50mW; TempCo: ppm/C; Value_Code: 0000; Value: 0; EIA_Code: E24; SizeX_mm: 0.6; SizeY_mm: 0.3; SizeZ_mm: 0.26; Value2: 0.05W; SizeArea_mm2: 0.18; AEC Qualified: N; AEC Category: Q200
R172 = CMP-0025960-3: RES, 10.5 k, 1%, 0.063 W, AEC-Q200 Grade 0, 0402; Manufacturer: Vishay-Dale; Power_W: 63mW; TempCo: 100 ppm/C; Value_Code: 10k5; Value: 10.5k; EIA_Code: E96; SizeX_mm: 1; SizeY_mm: 0.5; SizeZ_mm: 0.6; Value2: 0.063W; AEC Qualified: Y; VDC_V: 50V; AEC Category: Q200; AEC Grade: 0
R213 R214 R233 = CMP-0026992-3: RES, 0, 5%, 0.1 W, AEC-Q200 Grade 0, 0402; Manufacturer: Panasonic; Power_W: 100mW; TempCo: 600 ppm/C; Value_Code: 0000; EIA_Code: E24; SizeX_mm: 1; SizeY_mm: 0.5; SizeZ_mm: 0.6; Value2: 0.1W; AEC Qualified: Y; VDC_V: 50V; AEC Category: Q200; SizeAreaWB_mm2: 3
R217 R221 R227 R228 R231 R232 R235 R236 = CMP-0027021-3: RES, 10, 5%, 0.05 W, 0201; Manufacturer: Yageo America; Power_W: 50mW; TempCo: 350 ppm/C; Value_Code: 10R0; U/M: EA; Value: 10; EIA_Code: E24; SizeX_mm: 0.6; SizeY_mm: 0.3; SizeZ_mm: 0.26; Value2: 0.05W; SizeArea_mm2: 0.18; AEC Qualified: N; VDC_V: 25V; AEC Category: Q200
R271-R273 R326 R416 R417 = CMP-0025958-3: RES, 10.0 k, 1%, 0.063 W, AEC-Q200 Grade 0, 0402; Manufacturer: Vishay-Dale; Power_W: 63mW; TempCo: 100 ppm/C; Value_Code: 10k0; Value: 10.0k; EIA_Code: E96; Res_ohm: 10k; SizeX_mm: 1; SizeY_mm: 0.5; SizeZ_mm: 0.6; Value2: 0.063W; CompType: Resistor; AEC Qualified: Y; VDC_V: 50V; AEC Category: Q200; AEC Grade: 0; INSTALLATION: DNP
R276 R277 = CMP-0026244-2: RES, 2.94 k, 1%, 0.063 W, AEC-Q200 Grade 0, 0402; Manufacturer: Vishay-Dale; Power_W: 63mW; TempCo: 100 ppm/C; Value_Code: 2k94; Value: 2.94k; EIA_Code: E96; SizeX_mm: 1; SizeY_mm: 0.5; SizeZ_mm: 0.6; Value2: 0.063W; AEC Qualified: Y; VDC_V: 50V; AEC Category: Q200; AEC Grade: 0
R278 R279 = CMP-0025950-3: RES, 100 k, 1%, 0.063 W, AEC-Q200 Grade 0, 0402; Manufacturer: Vishay-Dale; Power_W: 63mW; TempCo: 100 ppm/C; Value: 100k; EIA_Code: E96; SizeX_mm: 1; SizeY_mm: 0.5; SizeZ_mm: 0.6; Value2: 0.063W; AEC Qualified: Y; VDC_V: 50V; AEC Category: Q200; AEC Grade: 0
R280 = CMP-0026890-5: RES, 2.2 k, 5%, 0.063 W, AEC-Q200 Grade 0, 0402; Manufacturer: Vishay-Dale; Power_W: 63mW; TempCo: 200 ppm/C; Value_Code: 2k20; Value: 2.2k; EIA_Code: E24; SizeX_mm: 1; SizeY_mm: 0.5; SizeZ_mm: 0.6; Value2: 0.063W; AEC Qualified: Y; VDC_V: 50V; AEC Category: Q200; AEC Grade: 0
R380 R381 R386 R392 = CMP-0026299-2: RES, 33.2, 1%, 0.063 W, AEC-Q200 Grade 0, 0402; Manufacturer: Vishay-Dale; Power_W: 63mW; TempCo: 100 ppm/C; Value_Code: 33R2; Value: 33.2; EIA_Code: E96; SizeX_mm: 1; SizeY_mm: 0.5; SizeZ_mm: 0.6; Value2: 0.063W; AEC Qualified: Y; VDC_V: 50V; AEC Category: Q200; AEC Grade: 0
TP1 TP4 = CMP-0078143-3: TEST POINT.  No entry in BOM.
TP7 TP9 = CMP-0055138-1: Test Point, Miniature, Black, TH; Manufacturer: Keystone; CNHeader: FALSE; Green_Lifecycle: Active; Green_REACh: Passed; ContactFinish: Silver; CT: TRUE
U28 = CMP-0005318-2: 2-Kb, 4-Kb, 8-Kb and 16-Kb I2C CMOS Serial EEPROM, SOIC-8; Manufacturer: ON Semiconductor; SizeAreaWB_mm2: 55.131; SizeZ_mm: 1.75; SizeX_mm: 5.99; SizeY_mm: 4.9; SizeArea_mm2: 29.351
U29 = CMP-0122080-1: Manufacturer: Texas Instruments; SizeZ_mm: 1.234mm; Standoff Height: 0.216mm
Y3 = CMP-0001431-1: 50 MHz ±15ppm Crystal 8pF 50 Ohms 4-SMD, No Lead; Manufacturer: NDK; Frequency Stability: 50ppm; Frequency_Fixed: 50MHz; SizeZ_mm: 0.5mm; AEC Qualified: Yes; AEC Grade: Grade 1; Esr: 50

## Sheet PROC196A_PWR_Reference.SchDoc
size 431 x 279 mm; Date: Not shown in title block; ApprovedBy: Not shown in title block; CheckedBy: Not shown in title block; Author: Not shown in title block; CompanyName: Not shown in title block; Engineer: Not shown in title block; Organization: Not shown in title block; Address1: Not shown in title block; Address2: Not shown in title block; Address3: Not shown in title block; Address4: Not shown in title block; DocumentNumber: 3; Revision: Use project parameter SCH_Rev; SheetNumber: 3; SheetTotal: 25; PageSetup: Record=PageOptions¦CenterHorizontal=True¦CenterVertical=True¦PrintScale=1.00¦XCorrection=1.00¦YCorrection=1.00¦PrintKind=0¦BorderSize=5000000¦LeftOffset=0¦BottomOffset=0¦Orientation=2¦PaperLength=1000¦PaperWidth=1000¦Scale=100¦PaperSource=15¦PrintQuality=600¦MediaType=1¦DitherType=10¦PaperKind=Letter¦PrintScaleMode=1
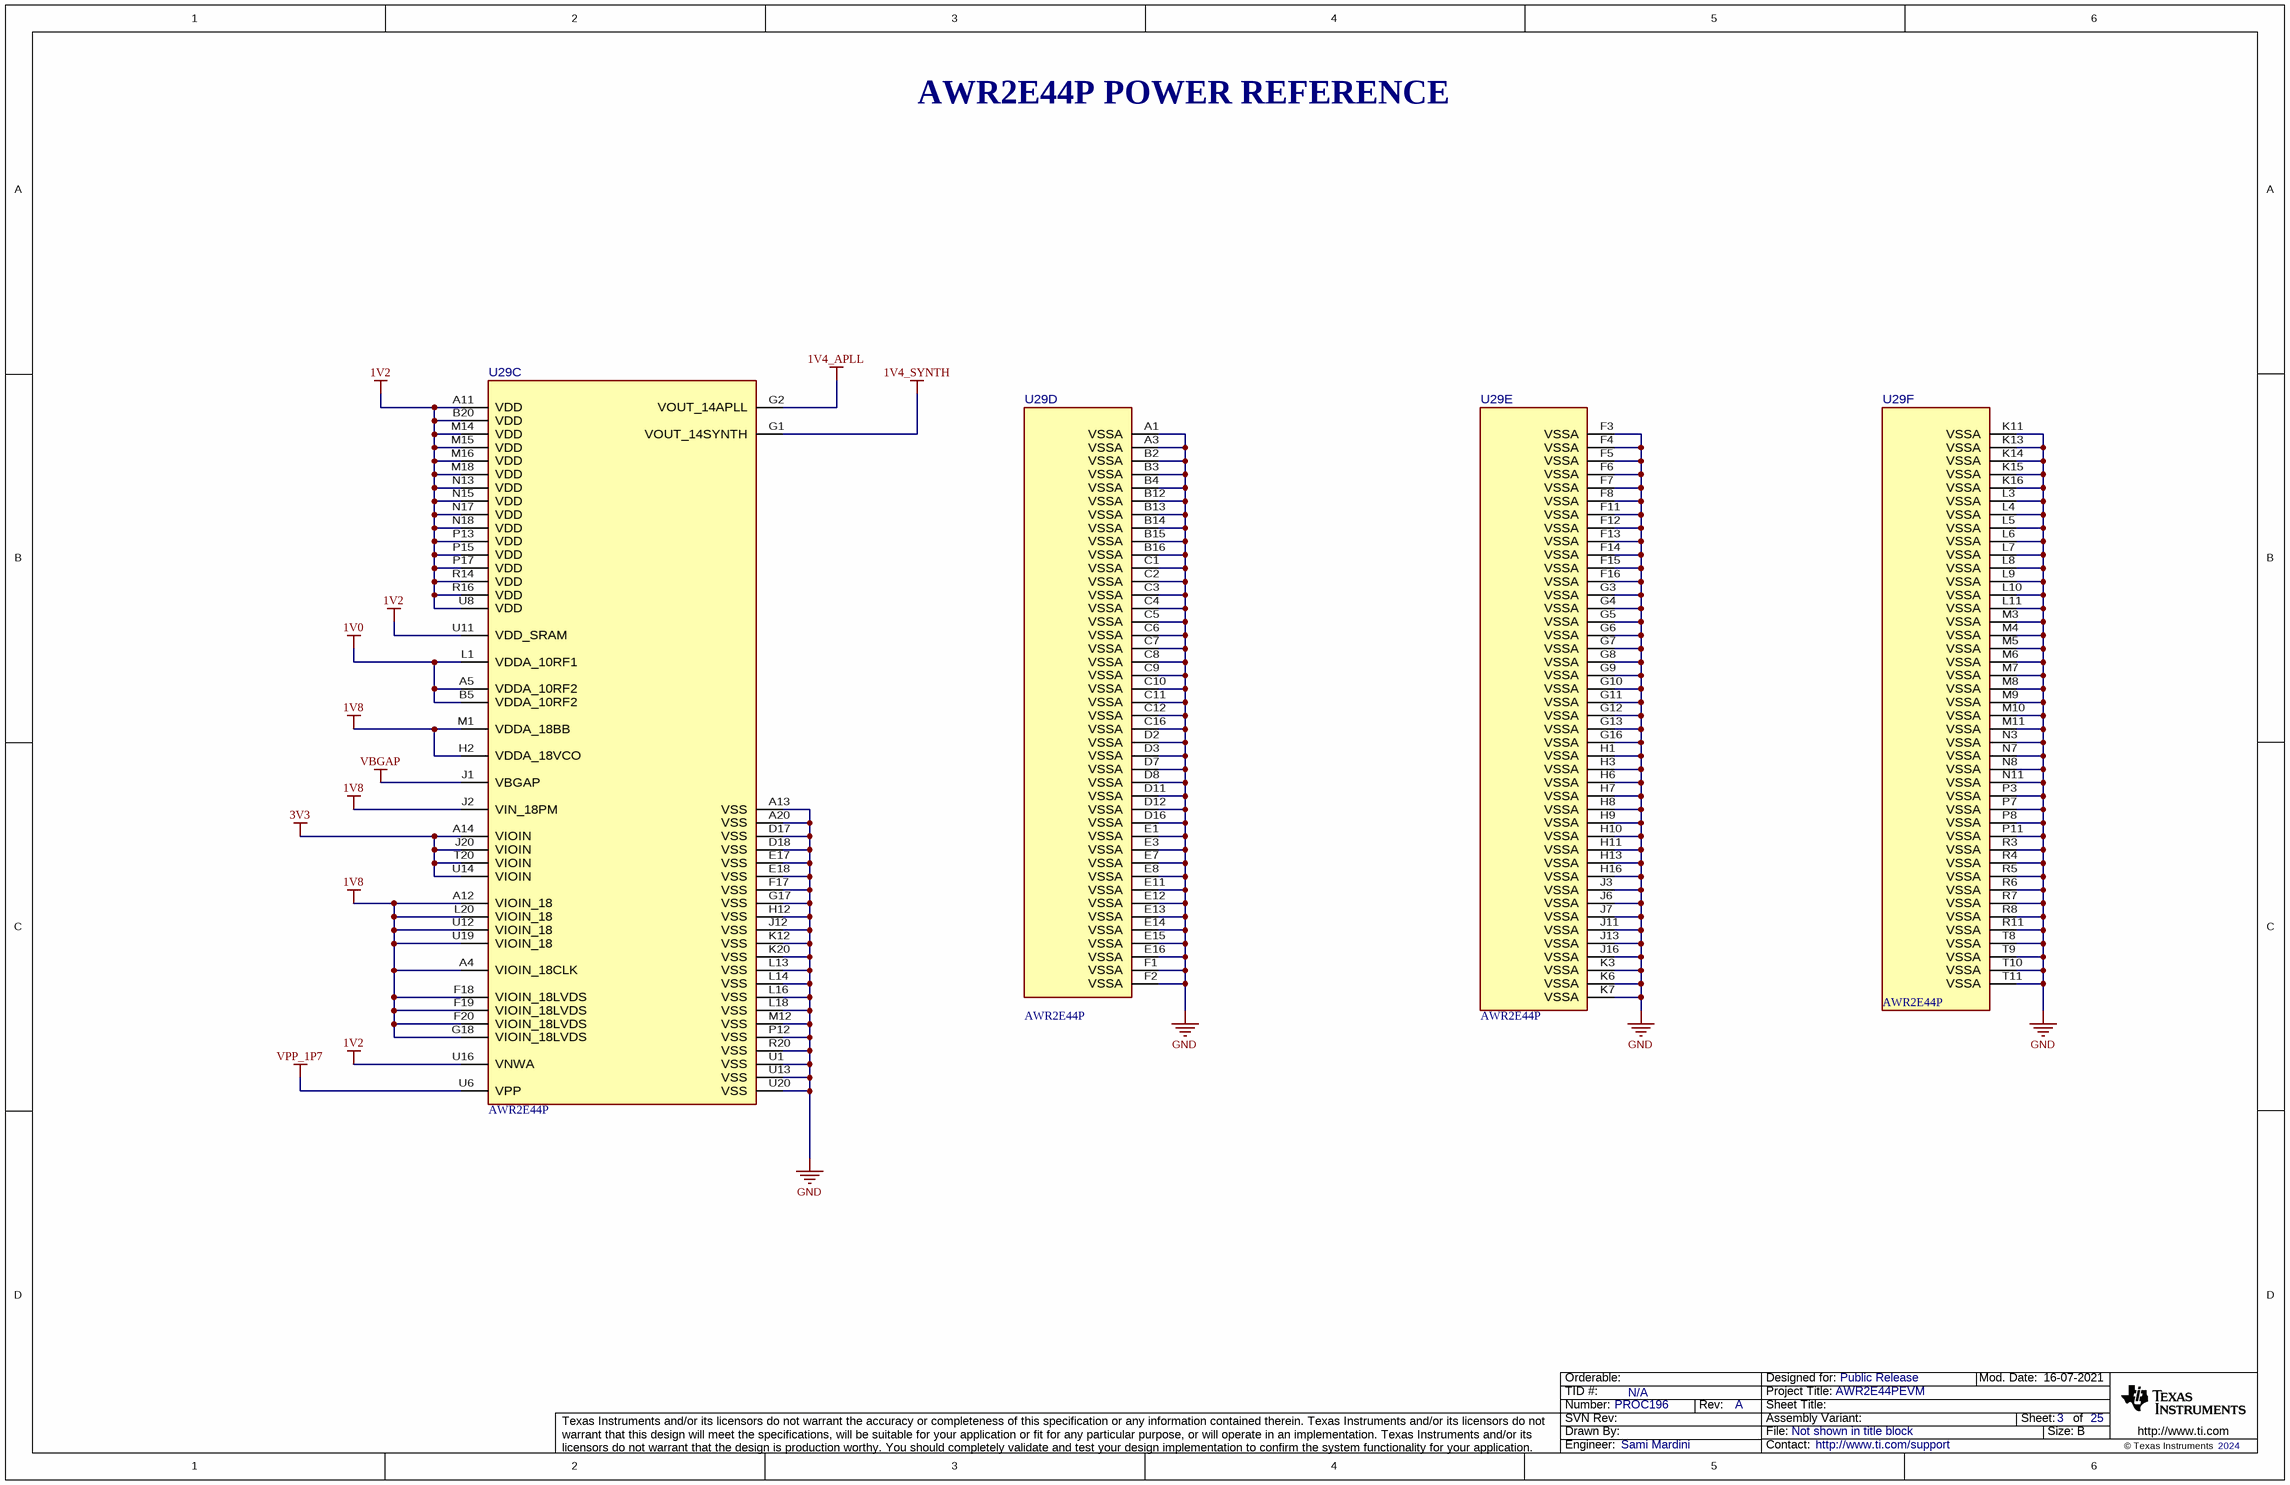
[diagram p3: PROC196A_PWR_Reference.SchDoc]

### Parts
U29  AWR2E44P  [AMX0278A-MFG]  (parts C,D,E,F of 6)

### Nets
1V0: U29.A5(VDDA_10RF2) U29.B5(VDDA_10RF2) U29.L1(VDDA_10RF1)
1V2: U29.A11(VDD) U29.B20(VDD) U29.M14(VDD) U29.M15(VDD) U29.M16(VDD) U29.M18(VDD) U29.N13(VDD) U29.N15(VDD) U29.N17(VDD) U29.N18(VDD) U29.P13(VDD) U29.P15(VDD) U29.P17(VDD) U29.R14(VDD) U29.R16(VDD) U29.U8(VDD) U29.U11(VDD_SRAM) U29.U16(VNWA)
1V4_APLL: U29.G2(VOUT_14APLL)
1V4_SYNTH: U29.G1(VOUT_14SYNTH)
1V8: U29.A4(VIOIN_18CLK) U29.A12(VIOIN_18) U29.F18(VIOIN_18LVDS) U29.F19(VIOIN_18LVDS) U29.F20(VIOIN_18LVDS) U29.G18(VIOIN_18LVDS) U29.H2(VDDA_18VCO) U29.J2(VIN_18PM) U29.L20(VIOIN_18) U29.M1(VDDA_18BB) U29.U12(VIOIN_18) U29.U19(VIOIN_18)
3V3: U29.A14(VIOIN) U29.J20(VIOIN) U29.T20(VIOIN) U29.U14(VIOIN)
GND: U29.A1(VSSA) U29.A3(VSSA) U29.A13(VSS) U29.A20(VSS) U29.B2(VSSA) U29.B3(VSSA) U29.B4(VSSA) U29.B12(VSSA) U29.B13(VSSA) U29.B14(VSSA) U29.B15(VSSA) U29.B16(VSSA) U29.C1(VSSA) U29.C2(VSSA) U29.C3(VSSA) U29.C4(VSSA) U29.C5(VSSA) U29.C6(VSSA) U29.C7(VSSA) U29.C8(VSSA) U29.C9(VSSA) U29.C10(VSSA) U29.C11(VSSA) U29.C12(VSSA) U29.C16(VSSA) U29.D2(VSSA) U29.D3(VSSA) U29.D7(VSSA) U29.D8(VSSA) U29.D11(VSSA) U29.D12(VSSA) U29.D16(VSSA) U29.D17(VSS) U29.D18(VSS) U29.E1(VSSA) U29.E3(VSSA) U29.E7(VSSA) U29.E8(VSSA) U29.E11(VSSA) U29.E12(VSSA) U29.E13(VSSA) U29.E14(VSSA) U29.E15(VSSA) U29.E16(VSSA) U29.E17(VSS) U29.E18(VSS) U29.F1(VSSA) U29.F2(VSSA) U29.F3(VSSA) U29.F4(VSSA) U29.F5(VSSA) U29.F6(VSSA) U29.F7(VSSA) U29.F8(VSSA) U29.F11(VSSA) U29.F12(VSSA) U29.F13(VSSA) U29.F14(VSSA) U29.F15(VSSA) U29.F16(VSSA) U29.F17(VSS) U29.G3(VSSA) U29.G4(VSSA) U29.G5(VSSA) U29.G6(VSSA) U29.G7(VSSA) U29.G8(VSSA) U29.G9(VSSA) U29.G10(VSSA) U29.G11(VSSA) U29.G12(VSSA) U29.G13(VSSA) U29.G16(VSSA) U29.G17(VSS) U29.H1(VSSA) U29.H3(VSSA) U29.H6(VSSA) U29.H7(VSSA) U29.H8(VSSA) U29.H9(VSSA) U29.H10(VSSA) U29.H11(VSSA) U29.H12(VSS) U29.H13(VSSA) U29.H16(VSSA) U29.J3(VSSA) U29.J6(VSSA) U29.J7(VSSA) U29.J11(VSSA) U29.J12(VSS) U29.J13(VSSA) U29.J16(VSSA) U29.K3(VSSA) U29.K6(VSSA) U29.K7(VSSA) U29.K11(VSSA) U29.K12(VSS) U29.K13(VSSA) U29.K14(VSSA) U29.K15(VSSA) U29.K16(VSSA) U29.K20(VSS) U29.L3(VSSA) U29.L4(VSSA) U29.L5(VSSA) U29.L6(VSSA) U29.L7(VSSA) U29.L8(VSSA) U29.L9(VSSA) U29.L10(VSSA) U29.L11(VSSA) U29.L13(VSS) U29.L14(VSS) U29.L16(VSS) U29.L18(VSS) U29.M3(VSSA) U29.M4(VSSA) U29.M5(VSSA) U29.M6(VSSA) U29.M7(VSSA) U29.M8(VSSA) U29.M9(VSSA) U29.M10(VSSA) U29.M11(VSSA) U29.M12(VSS) U29.N3(VSSA) U29.N7(VSSA) U29.N8(VSSA) U29.N11(VSSA) U29.P3(VSSA) U29.P7(VSSA) U29.P8(VSSA) U29.P11(VSSA) U29.P12(VSS) U29.R3(VSSA) U29.R4(VSSA) U29.R5(VSSA) U29.R6(VSSA) U29.R7(VSSA) U29.R8(VSSA) U29.R11(VSSA) U29.R20(VSS) U29.T8(VSSA) U29.T9(VSSA) U29.T10(VSSA) U29.T11(VSSA) U29.U1(VSS) U29.U13(VSS) U29.U20(VSS)
VBGAP: U29.J1(VBGAP)
VPP_1P7: U29.U6(VPP)

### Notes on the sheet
- AWR2E44P POWER REFERENCE

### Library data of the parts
U29 = CMP-0122080-1: as U29 on sheet PROC196A_IO_Reference

## Sheet PROC196A_Decoupling_Reference.SchDoc
size 431 x 279 mm; Date: Not shown in title block; ApprovedBy: Not shown in title block; CheckedBy: Not shown in title block; Author: Not shown in title block; CompanyName: Not shown in title block; Engineer: Not shown in title block; Organization: Not shown in title block; Address1: Not shown in title block; Address2: Not shown in title block; Address3: Not shown in title block; Address4: Not shown in title block; DocumentNumber: 4; Revision: Use project parameter SCH_Rev; SheetNumber: 4; SheetTotal: 25; PageSetup: Record=PageOptions¦CenterHorizontal=True¦CenterVertical=True¦PrintScale=1.00¦XCorrection=1.00¦YCorrection=1.00¦PrintKind=0¦BorderSize=5000000¦LeftOffset=0¦BottomOffset=0¦Orientation=2¦PaperLength=1000¦PaperWidth=1000¦Scale=100¦PaperSource=15¦PrintQuality=600¦MediaType=1¦DitherType=10¦PaperKind=Letter¦PrintScaleMode=1
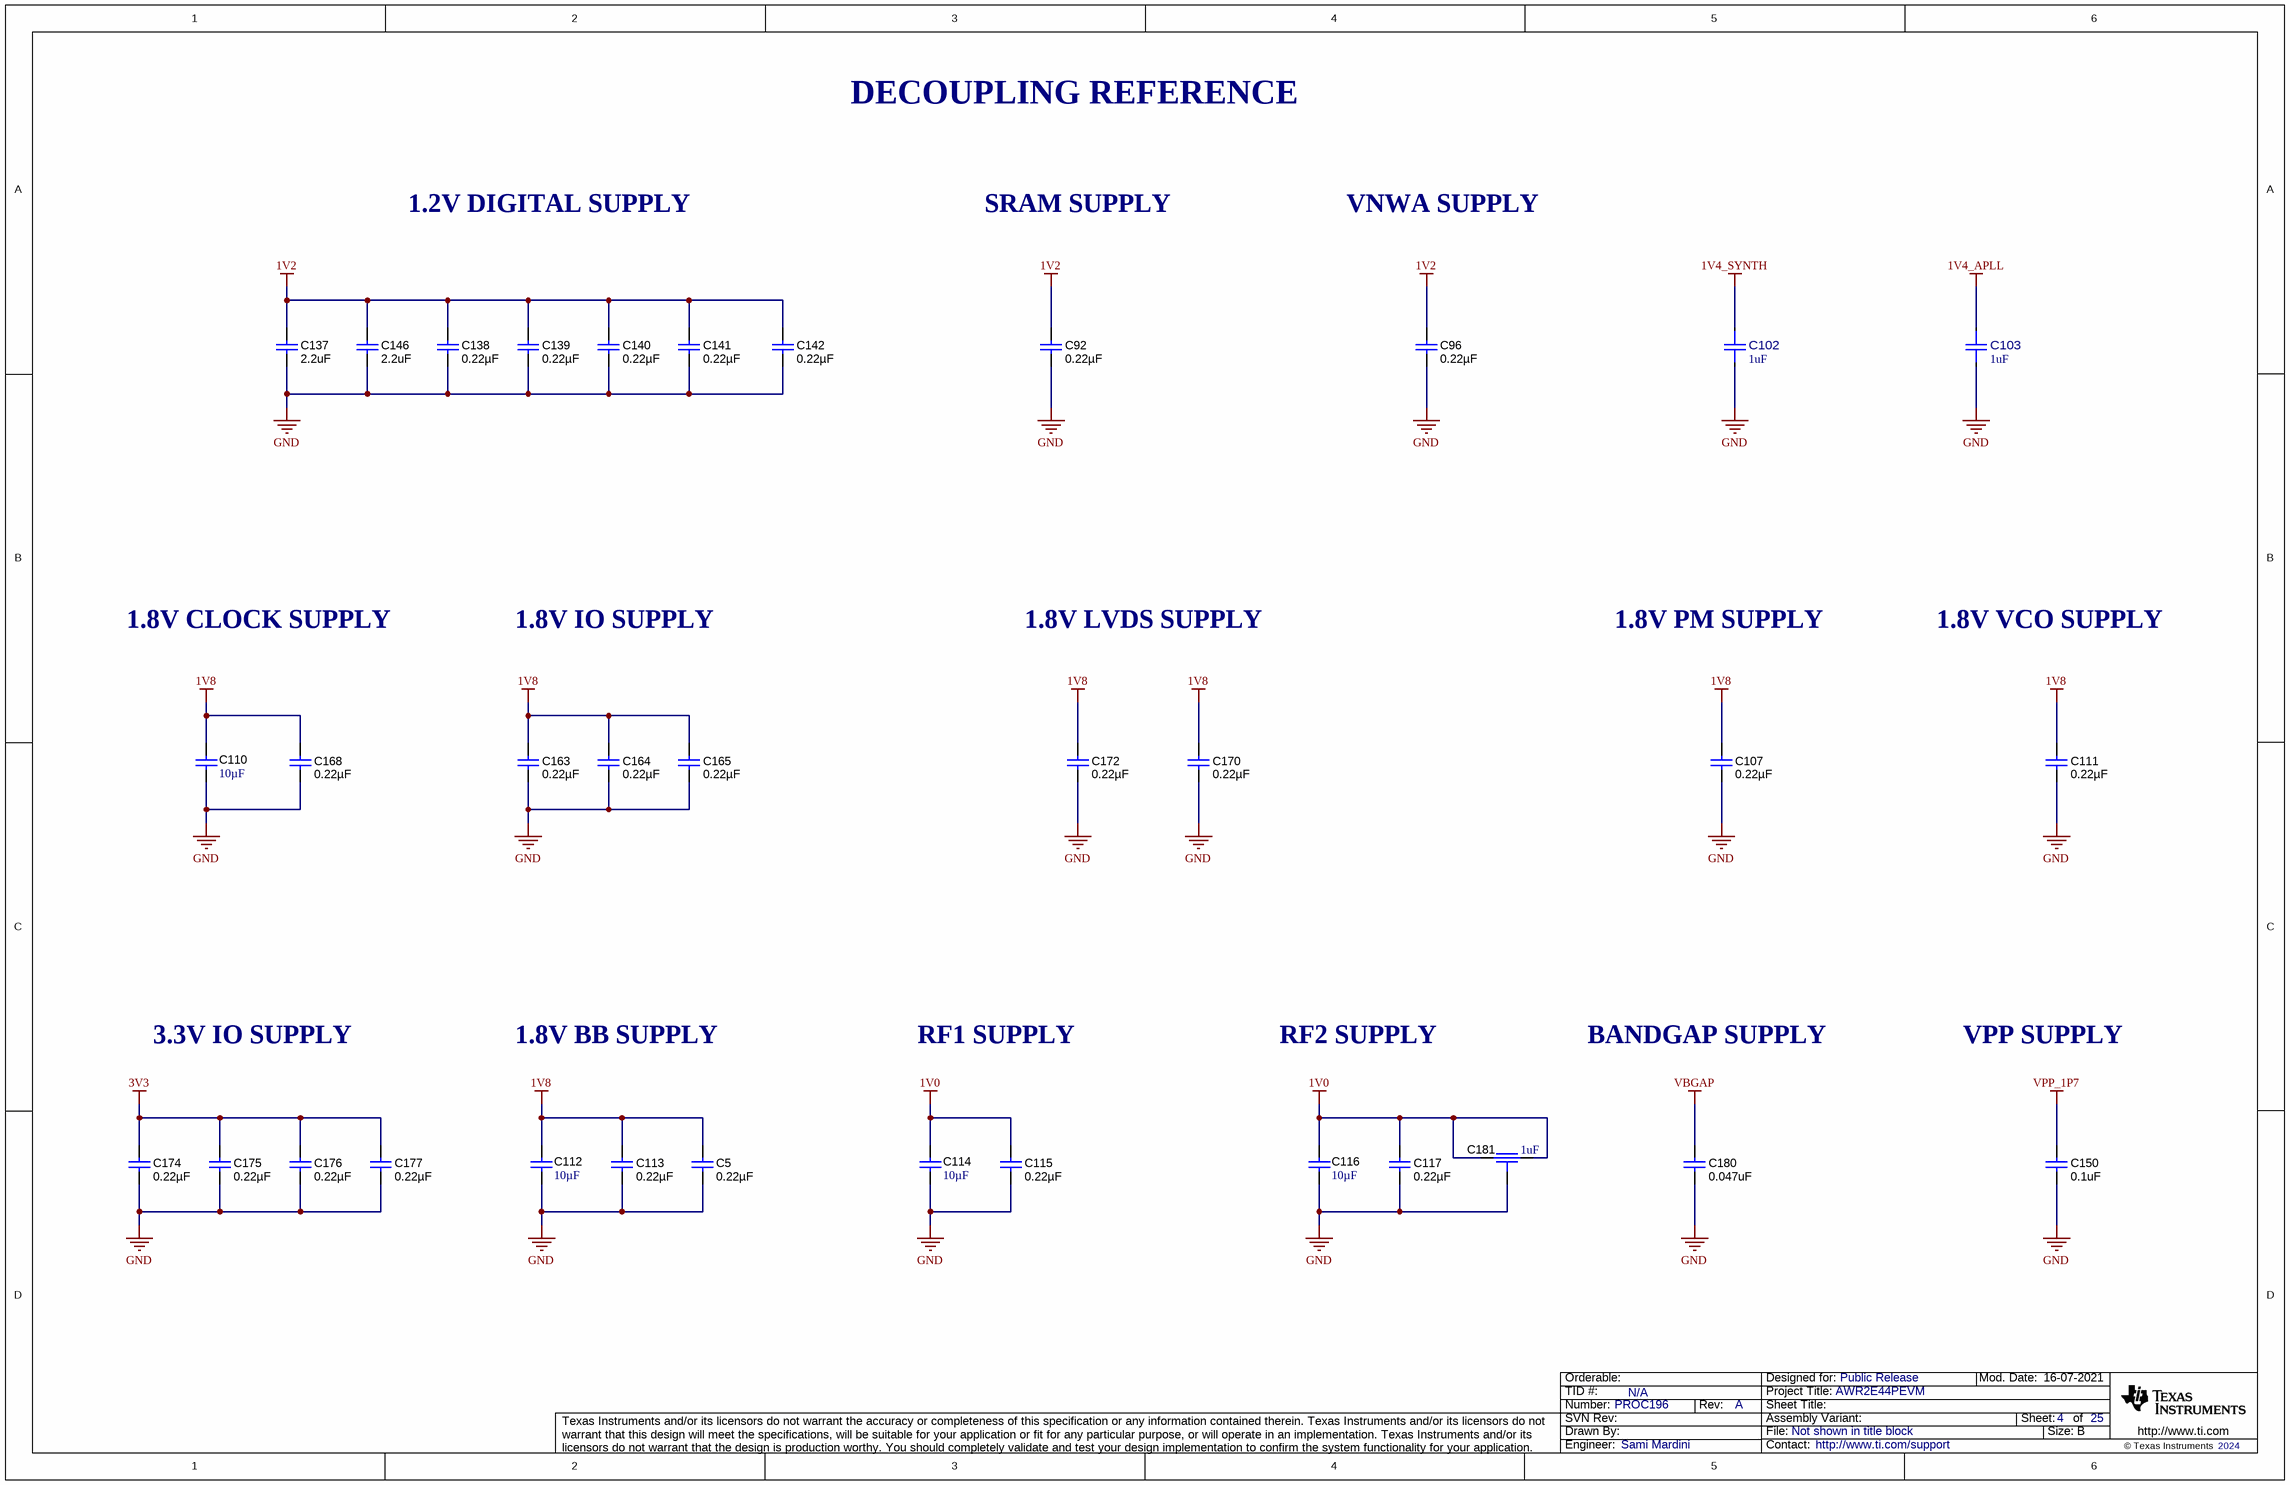
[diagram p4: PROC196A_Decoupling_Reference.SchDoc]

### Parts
C5  ValueDisplayed: 0.22µF  [0402L]  (hidden comment: GCM155R71C224KE02D)
C92  ValueDisplayed: 0.22µF  [0402L]  (hidden comment: GCM155R71C224KE02D)
C96  ValueDisplayed: 0.22µF  [0402L]  (hidden comment: GCM155R71C224KE02D)
C102  ValueDisplayed: 1uF  [FP-GRT155R70J105KE01D_0402-MFG]  (hidden comment: GRT155R70J105KE01D)
C103  ValueDisplayed: 1uF  [FP-GRT155R70J105KE01D_0402-MFG]  (hidden comment: GRT155R70J105KE01D)
C107  ValueDisplayed: 0.22µF  [0402L]  (hidden comment: GCM155R71C224KE02D)
C110  Cap_F: 10µF  [0805L]  (hidden comment: GCM21BR71A106KE22L)
C111  ValueDisplayed: 0.22µF  [0402L]  (hidden comment: GCM155R71C224KE02D)
C112  Cap_F: 10µF  [0805L]  (hidden comment: GCM21BR71A106KE22L)
C113  ValueDisplayed: 0.22µF  [0402L]  (hidden comment: GCM155R71C224KE02D)
C114  Cap_F: 10µF  [0805L]  (hidden comment: GCM21BR71A106KE22L)
C115  ValueDisplayed: 0.22µF  [0402L]  (hidden comment: GCM155R71C224KE02D)
C116  Cap_F: 10µF  [0805L]  (hidden comment: GCM21BR71A106KE22L)
C117  ValueDisplayed: 0.22µF  [0402L]  (hidden comment: GCM155R71C224KE02D)
C137  ValueDisplayed: 2.2uF  [0603L]  (hidden comment: GCM188R70J225KE22D)
C138  ValueDisplayed: 0.22µF  [0402L]  (hidden comment: GCM155R71C224KE02D)
C139  ValueDisplayed: 0.22µF  [0402L]  (hidden comment: GCM155R71C224KE02D)
C140  ValueDisplayed: 0.22µF  [0402L]  (hidden comment: GCM155R71C224KE02D)
C141  ValueDisplayed: 0.22µF  [0402L]  (hidden comment: GCM155R71C224KE02D)
C142  ValueDisplayed: 0.22µF  [0402L]  (hidden comment: GCM155R71C224KE02D)
C146  ValueDisplayed: 2.2uF  [0603L]  (hidden comment: GCM188R70J225KE22D)
C150  ValueDisplayed: 0.1uF  [0402L]  (hidden comment: GCM155R71C104KA55D)
C163  ValueDisplayed: 0.22µF  [0402L]  (hidden comment: GCM155R71C224KE02D)
C164  ValueDisplayed: 0.22µF  [0402L]  (hidden comment: GCM155R71C224KE02D)
C165  ValueDisplayed: 0.22µF  [0402L]  (hidden comment: GCM155R71C224KE02D)
C168  ValueDisplayed: 0.22µF  [0402L]  (hidden comment: GCM155R71C224KE02D)
C170  ValueDisplayed: 0.22µF  [0402L]  (hidden comment: GCM155R71C224KE02D)
C172  ValueDisplayed: 0.22µF  [0402L]  (hidden comment: GCM155R71C224KE02D)
C174  ValueDisplayed: 0.22µF  [0402L]  (hidden comment: GCM155R71C224KE02D)
C175  ValueDisplayed: 0.22µF  [0402L]  (hidden comment: GCM155R71C224KE02D)
C176  ValueDisplayed: 0.22µF  [0402L]  (hidden comment: GCM155R71C224KE02D)
C177  ValueDisplayed: 0.22µF  [0402L]  (hidden comment: GCM155R71C224KE02D)
C180  ValueDisplayed: 0.047uF  [0402L]  (hidden comment: CGA2B3X7R1H473K050BB)
C181  ValueDisplayed: 1uF  [FP-NFM18HC105C1C3D_0603-MFG]  (hidden comment: NFM18HC105C1C3D)

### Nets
1V0: C114.1 C115.2 C116.1 C117.2 C181.1 C181.3
1V2: C92.2 C96.2 C137.2 C138.2 C139.2 C140.2 C141.2 C142.2 C146.2
1V4_APLL: C103.1
1V4_SYNTH: C102.1
1V8: C5.2 C107.2 C110.1 C111.2 C112.1 C113.2 C163.2 C164.2 C165.2 C168.2 C170.2 C172.2
3V3: C174.2 C175.2 C176.2 C177.2
GND: C5.1 C92.1 C96.1 C102.2 C103.2 C107.1 C110.2 C111.1 C112.2 C113.1 C114.2 C115.1 C116.2 C117.1 C137.1 C138.1 C139.1 C140.1 C141.1 C142.1 C146.1 C150.1 C163.1 C164.1 C165.1 C168.1 C170.1 C172.1 C174.1 C175.1 C176.1 C177.1 C180.2 C181.2
VBGAP: C180.1
VPP_1P7: C150.2

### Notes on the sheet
- DECOUPLING REFERENCE
- 1.2V DIGITAL SUPPLY
- SRAM SUPPLY
- VNWA SUPPLY
- 1.8V CLOCK SUPPLY
- 1.8V IO SUPPLY
- 1.8V LVDS SUPPLY
- 1.8V PM SUPPLY
- 1.8V VCO SUPPLY
- 3.3V IO SUPPLY
- 1.8V BB SUPPLY
- RF1 SUPPLY
- RF2 SUPPLY
- BANDGAP SUPPLY
- VPP SUPPLY

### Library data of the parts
C5 C92 C96 C107 C111 C113 C115 C117 C138-C142 C163-C165 C168 C170 C172 C174-C177 = CMP-0078265-1: CAP, CERM, 0.22 µF, 16 V,+/- 10%, X7R, AEC-Q200 Grade 1, 0402; Manufacturer: MuRata; TaMin_C: -55°C; Polarized: N; SizeAreaWB_mm2: 3; U/M: EA; Value: 0.22uF; TaMax_C: 125°C; SizeZ_mm: 0.6; SizeX_mm: 1; SizeY_mm: 0.5; Cap_Case: 0402; Value2: 16V; CompType: Capacitor; AEC Qualified: Y; Cap_F: 220nF; AEC Category: Q200
C102 C103 = CMP-0088425-1: 1µF ±10% 6.3V Ceramic Capacitor X7R 0402 (1005 Metric); Manufacturer: Murata; AEC Grade: Grade 1; SizeZ_mm: 0.55mm; AEC Qualified: Yes; TempCo: 15%
C110 C112 C114 C116 = CMP-0008017-2: CAP, CERM, 10 uF, 10 V, +/- 10%, X7R, 0805; Manufacturer: MuRata; TaMin_C: -55°C; Polarized: N; SizeAreaWB_mm2: 6.75; Value1: Unknown; U/M: EA; Value: 10uF; TaMax_C: 125°C; SizeZ_mm: 1.45; SizeX_mm: 2; SizeY_mm: 1.25; Cap_Case: 0805; Value2: 10V; SizeArea_mm2: 2.5; AEC Category: Q200
C137 C146 = CMP-0007134-5: CAP, CERM, 2.2 uF, 6.3 V, +/- 10%, X7R, AEC-Q200 Grade 1, 0603; Manufacturer: MuRata; TaMin_C: -55°C; Polarized: N; SizeAreaWB_mm2: 4.68; Value1: Unknown; U/M: EA; Value: 2.2uF; TaMax_C: 125°C; SizeZ_mm: 1; SizeX_mm: 1.6; SizeY_mm: 0.8; Cap_Case: 0603; Value2: 6.3V; SizeArea_mm2: 1.28; AEC Qualified: Y; Cap_F: 2.2µF; AEC Category: Q200
C150 = CMP-0006351-2: CAP, CERM, 0.1 uF, 16 V, +/- 10%, X7R, 0402; Manufacturer: MuRata; TaMin_C: -55°C; Polarized: N; SizeAreaWB_mm2: 3; Value1: Unknown; U/M: EA; Value: 0.1uF; TaMax_C: 125°C; SizeZ_mm: 0.6; SizeX_mm: 1; SizeY_mm: 0.5; Cap_Case: 0402; Value2: 16V; Cap_F: 100nF; AEC Category: Q200
C180 = CMP-0006330-2: CAP, CERM, 0.047 uF, 50 V, +/- 10%, X7R, AEC-Q200 Grade 1, 0402; Manufacturer: TDK; TaMin_C: -55°C; ESR_ohm: 0.06407; Polarized: N; SizeAreaWB_mm2: 3; Value1: 0.06407 ohm; U/M: EA; TaMax_C: 125°C; SizeZ_mm: 0.6; SizeX_mm: 1; SizeY_mm: 0.5; Cap_Case: 0402; Value2: 50V; AEC Qualified: Y; Cap_F: 47nF; IRMS_A: 646.122mA; AEC Category: Q200
C181 = CMP-0088247-2: 3 Terminals Low ESL Chip Multilayer Ceramic Capacitors for Automotive; Manufacturer: Murata; VDC_V: 16V; SizeZ_mm: 0.7mm; Tolerance_%: 20%; AEC Grade: Grade 1; Cap_F: 1µF; AEC Qualified: Yes

## Sheet PROC196A_QSPI_Flash_Reference.SchDoc
size 431 x 279 mm; Date: Not shown in title block; ApprovedBy: Not shown in title block; CheckedBy: Not shown in title block; Author: Not shown in title block; CompanyName: Not shown in title block; Engineer: Not shown in title block; Organization: Not shown in title block; Address1: Not shown in title block; Address2: Not shown in title block; Address3: Not shown in title block; Address4: Not shown in title block; DocumentNumber: 5; Revision: Use project parameter SCH_Rev; SheetNumber: 5; SheetTotal: 25; PageSetup: Record=PageOptions¦CenterHorizontal=True¦CenterVertical=True¦PrintScale=1.00¦XCorrection=1.00¦YCorrection=1.00¦PrintKind=0¦BorderSize=5000000¦LeftOffset=0¦BottomOffset=0¦Orientation=2¦PaperLength=1000¦PaperWidth=1000¦Scale=100¦PaperSource=15¦PrintQuality=600¦MediaType=1¦DitherType=10¦PaperKind=Letter¦PrintScaleMode=1
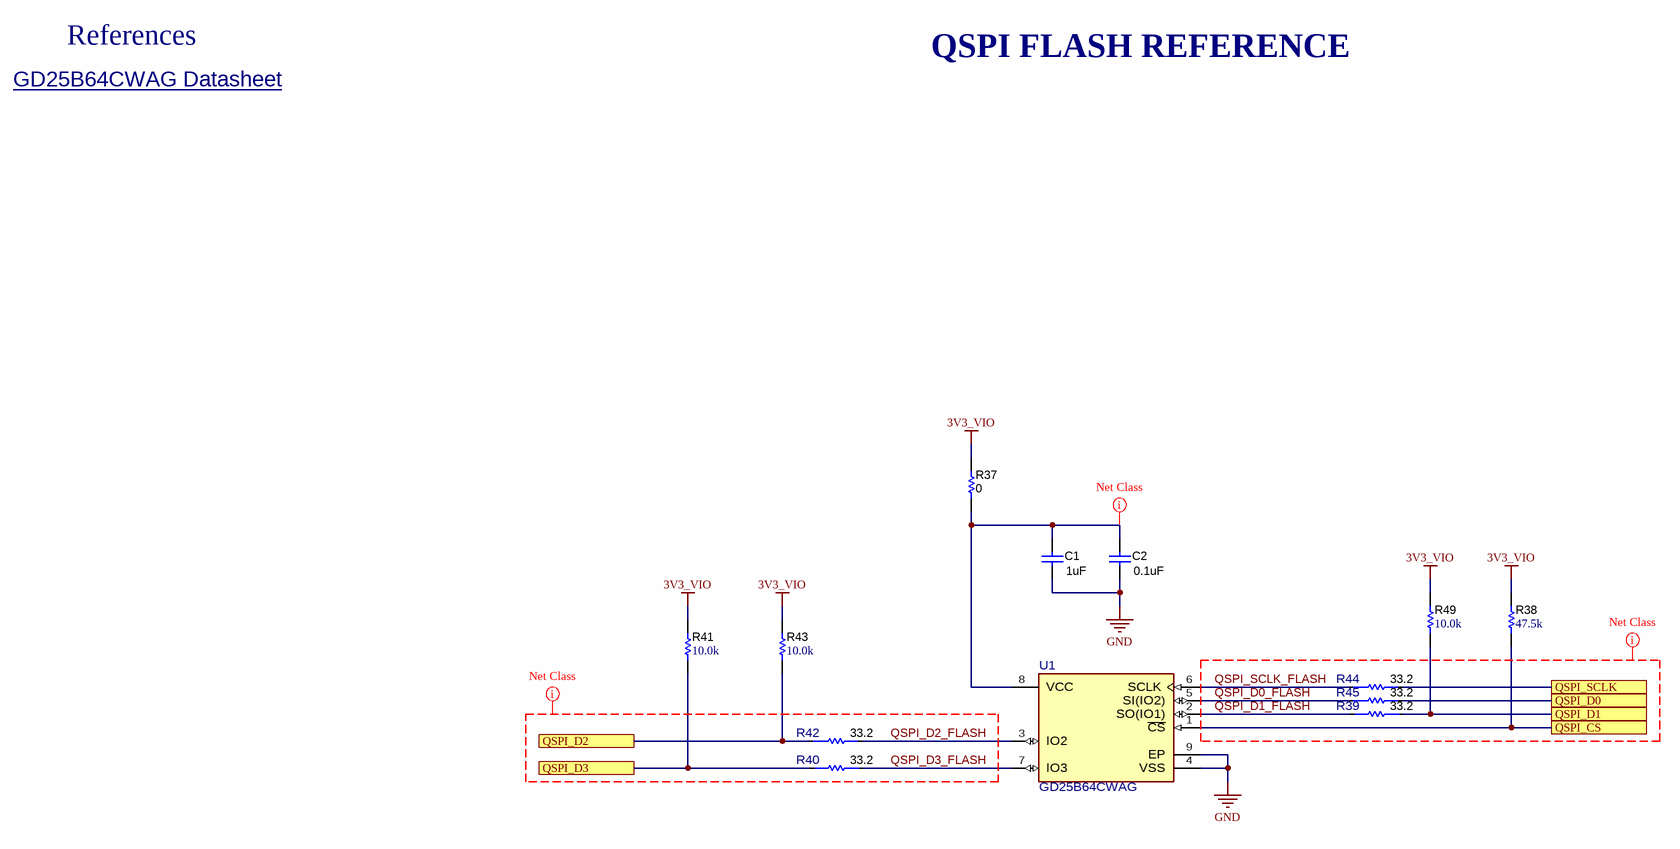
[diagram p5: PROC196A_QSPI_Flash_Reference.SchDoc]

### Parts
C1  ValueDisplayed: 1uF  [0603L]  (hidden comment: GCM188R71C105KA64D)
C2  ValueDisplayed: 0.1uF  [0402L]  (hidden comment: CGA2B3X7R1H104K050BB)
R37  ValueDisplayed: 0  [0402L]  (hidden comment: ERJ-2GE0R00X)
R38  ValueDisplayed: 47.5k  [0402L]  (hidden comment: CRCW040247K5FKED)
R39  Res_ohm: 33.2  [FP-ERJ-1GNF33R2C_0201-MFG]  (hidden comment: ERJ-1GNF33R2C)
R40  Res_ohm: 33.2  [FP-ERJ-1GNF33R2C_0201-MFG]  (hidden comment: ERJ-1GNF33R2C)
R41  ValueDisplayed: 10.0k  [0402L]  (hidden comment: CRCW040210K0FKED)
R42  Res_ohm: 33.2  [FP-ERJ-1GNF33R2C_0201-MFG]  (hidden comment: ERJ-1GNF33R2C)
R43  ValueDisplayed: 10.0k  [0402L]  (hidden comment: CRCW040210K0FKED)
R44  Res_ohm: 33.2  [FP-ERJ-1GNF33R2C_0201-MFG]  (hidden comment: ERJ-1GNF33R2C)
R45  Res_ohm: 33.2  [FP-ERJ-1GNF33R2C_0201-MFG]  (hidden comment: ERJ-1GNF33R2C)
R49  ValueDisplayed: 10.0k  [0402L]  (hidden comment: CRCW040210K0FKED)
U1  GD25B64CWAG  [FP-GD25B64CWAG_WSON8-IPC_C]

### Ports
QSPI_CS, QSPI_D0, QSPI_D1, QSPI_D2, QSPI_D3, QSPI_SCLK

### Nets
3V3_VIO: R37.1 R38.2 R41.2 R43.2 R49.2
GND: C1.1 C2.1 U1.4(VSS) U1.9(EP)
QSPI_CS: R38.1 U1.1(~{CS}) ; port QSPI_CS
QSPI_D0: R45.2 ; port QSPI_D0
QSPI_D0_FLASH: R45.1 U1.5(SI(IO2))
QSPI_D1: R39.1 R49.1 ; port QSPI_D1
QSPI_D1_FLASH: R39.2 U1.2(SO(IO1))
QSPI_D2: R42.1 R43.1 ; port QSPI_D2
QSPI_D2_FLASH: R42.2 U1.3(IO2)
QSPI_D3: R40.2 R41.1 ; port QSPI_D3
QSPI_D3_FLASH: R40.1 U1.7(IO3)
QSPI_SCLK: R44.2 ; port QSPI_SCLK
QSPI_SCLK_FLASH: R44.1 U1.6(SCLK)
NetC1_2: C1.2 C2.2 R37.2 U1.8(VCC)

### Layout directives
net class QSPI: QSPI_D0_FLASH, QSPI_D1_FLASH, QSPI_D2_FLASH, QSPI_D3_FLASH, QSPI_SCLK_FLASH
net class PWR: NetC1_2

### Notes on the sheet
- References
- QSPI FLASH REFERENCE
- GD25B64CWAG Datasheet <https://www.gigadevice.com/datasheet/gd25b64c/>

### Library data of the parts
C1 = CMP-0007136-5: CAP, CERM, 1 uF, 16 V, +/- 10%, X7R, AEC-Q200 Grade 1, 0603; Manufacturer: MuRata; TaMin_C: -55°C; Polarized: N; SizeAreaWB_mm2: 4.68; Value1: Unknown; U/M: EA; Value: 1uF; TaMax_C: 125°C; SizeZ_mm: 1; SizeX_mm: 1.6; SizeY_mm: 0.8; Cap_Case: 0603; Value2: 16V; SizeArea_mm2: 1.28; AEC Qualified: Y; Cap_F: 1µF; AEC Category: Q200
C2 = CMP-0006325-2: CAP, CERM, 0.1 uF, 50 V, +/- 10%, X7R, AEC-Q200 Grade 1, 0402; Manufacturer: TDK; TaMin_C: -55°C; ESR_ohm: 0.039064; Polarized: N; SizeAreaWB_mm2: 3; Value1: 0.039064 ohm; U/M: EA; Value: 0.1uF; TaMax_C: 125°C; SizeZ_mm: 0.6; SizeX_mm: 1; SizeY_mm: 0.5; Cap_Case: 0402; Value2: 50V; AEC Qualified: Y; Cap_F: 100nF; IRMS_A: 8.14669dA; AEC Category: Q200
R37 = CMP-0026992-3: as R3 on sheet PROC196A_IO_Reference
R38 = CMP-0026395-2: RES, 47.5 k, 1%, 0.063 W, AEC-Q200 Grade 0, 0402; Manufacturer: Vishay-Dale; Power_W: 63mW; TempCo: 100 ppm/C; Value_Code: 47k5; Value: 47.5k; EIA_Code: E96; SizeX_mm: 1; SizeY_mm: 0.5; SizeZ_mm: 0.6; Value2: 0.063W; AEC Qualified: Y; VDC_V: 50V; AEC Category: Q200; AEC Grade: 0
R39 R40 R42 R44 R45 = CMP-0089575-2: Res Thick Film 0201 33.2 Ohm 1% 0.05W(1/20W) ±200ppm/C Pad SMD Automotive T/R; Manufacturer: Panasonic; TempCo: 200ppm/°C; VDC_V: 25V; AEC Qualified: Yes; SizeZ_mm: 0.26mm; Power_W: 50mW; AEC Grade: Grade 1; Value: 33.2
R41 R43 R49 = CMP-0025958-3: RES, 10.0 k, 1%, 0.063 W, AEC-Q200 Grade 0, 0402; Manufacturer: Vishay-Dale; Power_W: 63mW; TempCo: 100 ppm/C; Value_Code: 10k0; Value: 10.0k; EIA_Code: E96; Res_ohm: 10k; SizeX_mm: 1; SizeY_mm: 0.5; SizeZ_mm: 0.6; Value2: 0.063W; AEC Qualified: Y; VDC_V: 50V; AEC Category: Q200; AEC Grade: 0
U1 = CMP-0091081-1: 3.3V Uniform Sector Dual and Quad Serial Flash SPI 64Mbit 2.7-3.6V WSON8; Manufacturer: GigaDevice; Interface: SPI,Other; Min Supply Voltage: 2.7V; TaMin_C: -40°C; AEC Grade: Grade 1; Memory Size: 64Mbits; Frequency_Fixed: 120MHz; TaMax_C: +125°C; SizeZ_mm: 0.8mm; Standoff Height: 0mm; AEC Qualified: Yes; Nominal Supply Current: 13-15mA; Max Supply Voltage: 3.6V; Access Time: 7ns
